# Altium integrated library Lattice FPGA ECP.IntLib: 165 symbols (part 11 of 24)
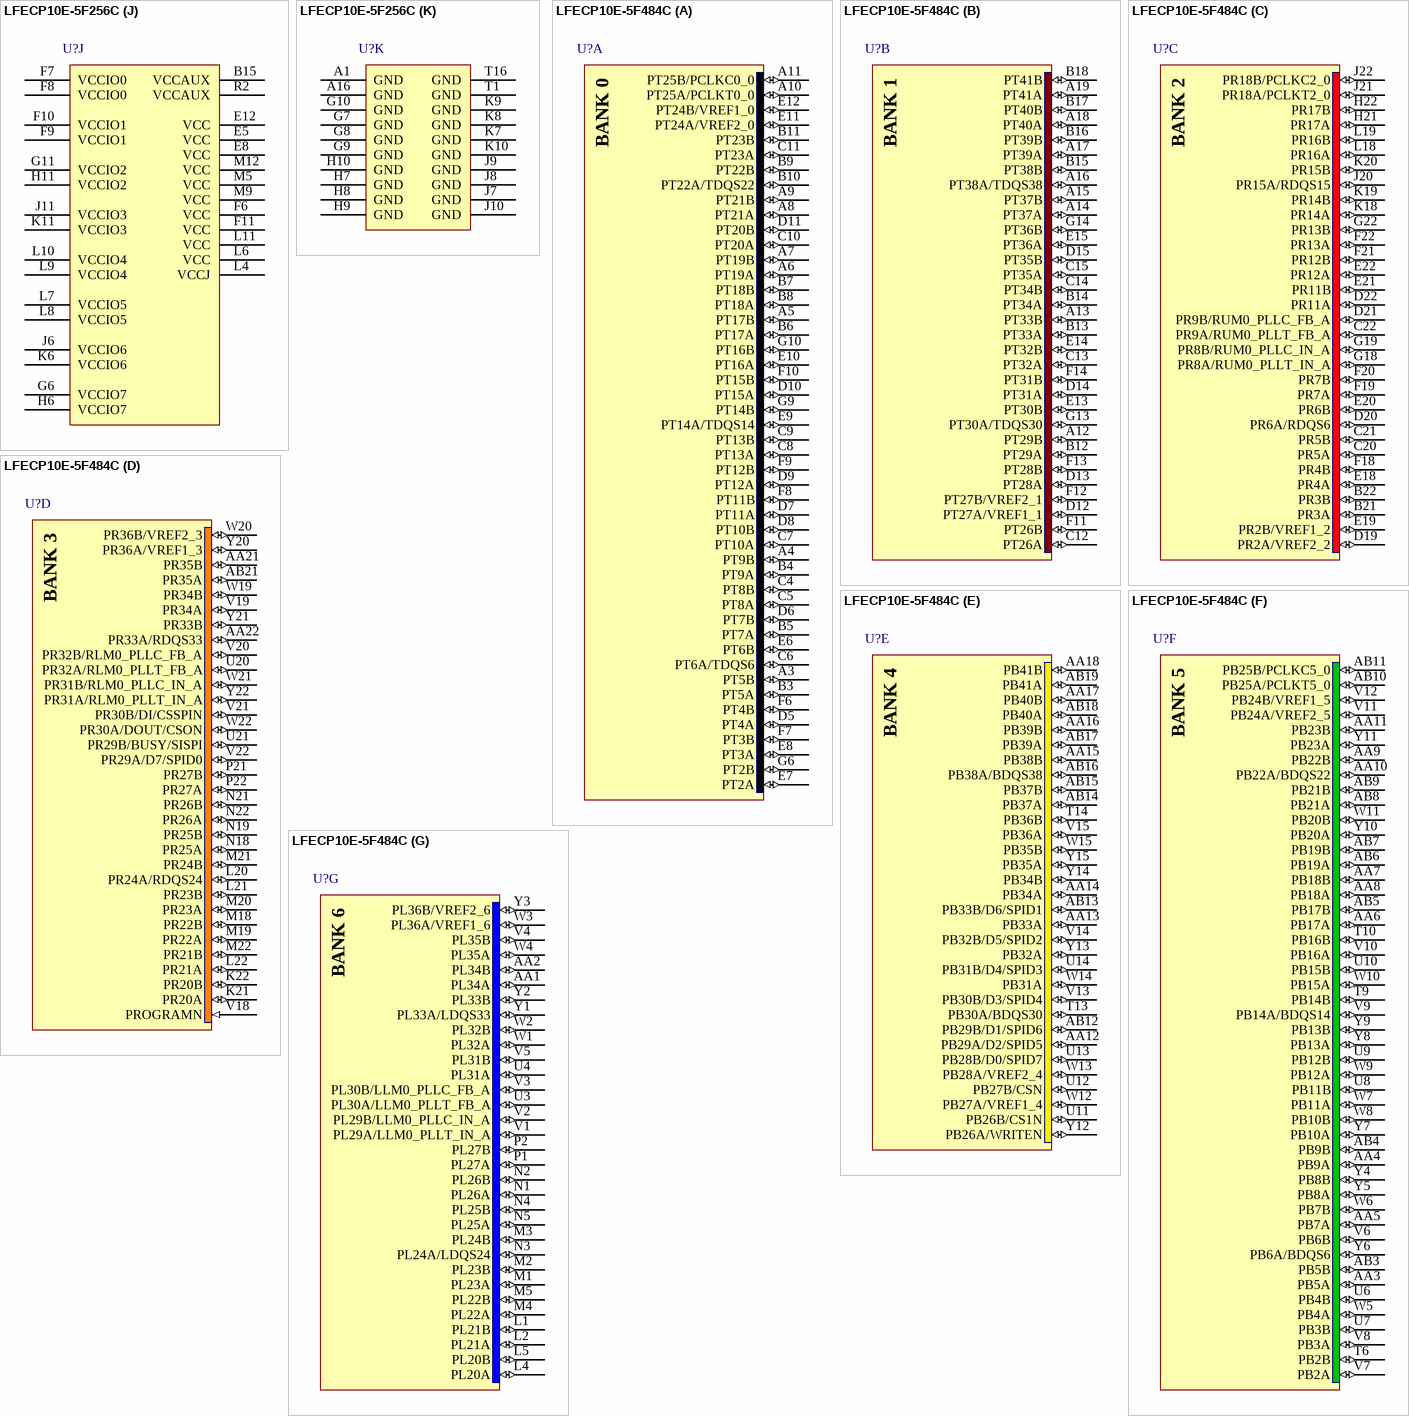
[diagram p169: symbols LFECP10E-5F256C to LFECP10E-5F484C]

## LFECP10E-5F256C
designator U?
ECP 1.2V FPGA, 192 I/Os, 4 PLLs, 10.2K LUTs, 5 sysDSP Blocks, 20 18x18 Multipliers, 256-Pin fpBGA, Speed Grade 5, Commercial Temperature Grade
footprint fpBGA256 (BGA, 256-Leads, Body 17x17mm, Pitch 1mm)
3D model ECP10E-fpBGA256 (256-Ball Fine Pitch Ball Grid Array (fpBGA256))
part A pins: A2 PT13A (io), A3 PT13B (io), A4 PT14A/TDQS14 (io), A5 PT14B (io), A6 PT18A (io), A7 PT18B (io), A8 PT21A (io), A9 PT21B (io), A10 PT25B/PCLKC0_0 (io), B2 PT12B (io), B3 PT12A (io), B4 PT10A (io), B5 PT15A (io), B6 PT15B (io), B7 PT20A (io), B8 PT20B (io), B9 PT24A/VREF2_0 (io), B10 PT25A/PCLKT0_0 (io), C4 PT10B (io), C5 PT11A (io), C6 PT16A (io), C7 PT19A (io), C8 PT22A/TDQS22 (io), C9 PT24B/VREF1_0 (io), D5 PT11B (io), D6 PT16B (io), D7 PT19B (io), D8 PT22B (io), D9 PT23A (io), E6 PT17A (io), E7 PT17B (io), E9 PT23B (io)
part B pins: A11 PT26B (io), A12 PT27B/VREF2_1 (io), A13 PT29A (io), A14 PT29B (io), A15 PT32B (io), B11 PT26A (io), B12 PT27A/VREF1_1 (io), B13 PT34B (io), B14 PT32A (io), C10 PT28A (io), C11 PT31A (io), C12 PT33B (io), C13 PT34A (io), D10 PT28B (io), D11 PT31B (io), D12 PT33A (io), E10 PT30B (io), E11 PT30A/TDQS30 (io)
part C pins: B16 PR13A (io), C14 PR12A (io), C15 PR12B (io), C16 PR13B (io), D13 PR2A/VREF2_2 (io), D14 PR2B/VREF1_2 (io), D15 PR15A (io), D16 PR15B (io), E13 PR16A (io), E14 PR14A (io), F12 PR16B (io), F13 PR17A (io), F14 PR14B (io), G12 PR18A/PCLKT2_0 (io), G13 PR17B (io), H12 PR18B/PCLKC2_0 (io)
part D pins: E15 PR20A (io), E16 PR20B (io), F15 PR23A (io), F16 PR23B (io), G14 PR21A (io), G15 PR26A (io), G16 PR26B (io), H13 PR22A (io), H14 PR21B (io), H15 PR27A (io), H16 PR27B (io), J12 PR25A (io), J13 PR22B (io), J14 PR24B (io), J15 PR24A/RDQS24 (io), J16 PR29A/D7/SPID0 (io), K12 PR25B (io), K16 PR29B/BUSY/SISPI (io), L16 PR30A/DOUT/CSON (io), M13 PR33B (io), M14 PR33A/RDQS33 (io), M15 PR31A/RLM0_PLLT_IN_A (io), M16 PR30B/DI/CSSPIN (io), N13 PR36B/VREF2_3 (io), N14 PR36A/VREF1_3 (io), N15 PR31B/RLM0_PLLC_IN_A (io), N16 PR32A/RLM0_PLLT_FB_A (io), P14 PR35B (io), P15 PR35A (io), P16 PR32B/RLM0_PLLC_FB_A (io), R15 PR34B (io), R16 PR34A (io)
part E pins: M10 PB29A/D2/SPID5 (io), M11 PB29B/D1/SPID6 (io), N10 PB27B/CSN (io), N11 PB33A (io), N12 PB33B/D6/SPID1 (io), P10 PB27A/VREF1_4 (io), P11 PB30B/D3/SPID4 (io), P12 PB32A (io), P13 PB32B/D5/SPID2 (io), R11 PB30A/BDQS30 (io), R12 PB34A (io), R13 PB31A (io), R14 PB31B/D4/SPID3 (io), T12 PB26A/WRITEN (io), T13 PB26B/CS1N (io), T14 PB28A/VREF2_4 (io), T15 PB28B/D0/SPID7 (io)
part F pins: M6 PB16B (io), M7 PB20A (io), M8 PB20B (io), N5 PB10B (io), N6 PB16A (io), N7 PB18B (io), N8 PB22B (io), N9 PB24B/VREF1_5 (io), P4 PB10A (io), P5 PB11A (io), P6 PB11B (io), P7 PB18A (io), P8 PB22A/BDQS22 (io), P9 PB24A/VREF2_5 (io), R3 PB12B (io), R4 PB12A (io), R5 PB14A/BDQS14 (io), R6 PB14B (io), R7 PB19A (io), R8 PB19B (io), R9 PB23A (io), R10 PB23B (io), T2 PB13A (io), T3 PB13B (io), T4 PB15A (io), T5 PB15B (io), T6 PB17A (io), T7 PB17B (io), T8 PB21A (io), T9 PB21B (io), T10 PB25A/PCLKT5_0 (io), T11 PB25B/PCLKC5_0 (io)
part G pins: F1 PL21B (io), F2 PL21A (io), G1 PL23B (io), G2 PL23A (io), G5 PL20A (io), H1 PL26B (io), H2 PL26A (io), H3 PL22B (io), H4 PL22A (io), H5 PL20B (io), J1 PL27B (io), J2 PL27A (io), J3 PL24B (io), J4 PL24A/LDQS24 (io), J5 PL25A (io), K1 PL29B/LLM0_PLLC_IN_A (io), K2 PL29A/LLM0_PLLT_IN_A (io), K5 PL25B (io), L1 PL30B/LLM0_PLLC_FB_A (io), L2 PL30A/LLM0_PLLT_FB_A (io), M1 PL31B (io), M2 PL31A (io), M3 PL33B (io), M4 PL33A/LDQS33 (io), N1 PL32A (io), N2 PL32B (io), N3 PL36A/VREF1_6 (io), N4 PL36B/VREF2_6 (io), P1 PL34A (io), P2 PL35A (io), P3 PL35B (io), R1 PL34B (io)
part H pins: B1 PL13A (io), C1 PL13B (io), C2 PL12B (io), C3 PL12A (io), D1 PL17B (io), D2 PL17A (io), D3 PL2B/VREF1_7 (io), D4 PL2A/VREF2_7 (io), E1 PL18A/PCLKT7_0 (io), E2 PL18B/PCLKC7_0 (io), E3 PL14A (io), E4 PL14B (io), F4 PL15A/LDQS15 (io), F5 PL15B (io), G3 PL16B (io), G4 PL16A (io)
part I pins: F3 XRES, K3 TDI (in), K4 TCK (in), K13 PROGRAMN (in), K14 DONE (io), K15 INITN (io), L3 TMS (in), L5 TDO (out), L12 CFG2 (in), L13 CFG0 (in), L14 CFG1 (in), L15 CCLK (io)
part J pins: B15 VCCAUX (power), E5 VCC (power), E8 VCC (power), E12 VCC (power), F6 VCC (power), F7 VCCIO0 (power), F8 VCCIO0 (power), F9 VCCIO1 (power), F10 VCCIO1 (power), F11 VCC (power), G6 VCCIO7 (power), G11 VCCIO2 (power), H6 VCCIO7 (power), H11 VCCIO2 (power), J6 VCCIO6 (power), J11 VCCIO3 (power), K6 VCCIO6 (power), K11 VCCIO3 (power), L4 VCCJ (power), L6 VCC (power), L7 VCCIO5 (power), L8 VCCIO5 (power), L9 VCCIO4 (power), L10 VCCIO4 (power), L11 VCC (power), M5 VCC (power), M9 VCC (power), M12 VCC (power), R2 VCCAUX (power)
part K pins: A1 GND (power), A16 GND (power), G7 GND (power), G8 GND (power), G9 GND (power), G10 GND (power), H7 GND (power), H8 GND (power), H9 GND (power), H10 GND (power), J7 GND (power), J8 GND (power), J9 GND (power), J10 GND (power), K7 GND (power), K8 GND (power), K9 GND (power), K10 GND (power), T1 GND (power), T16 GND (power)

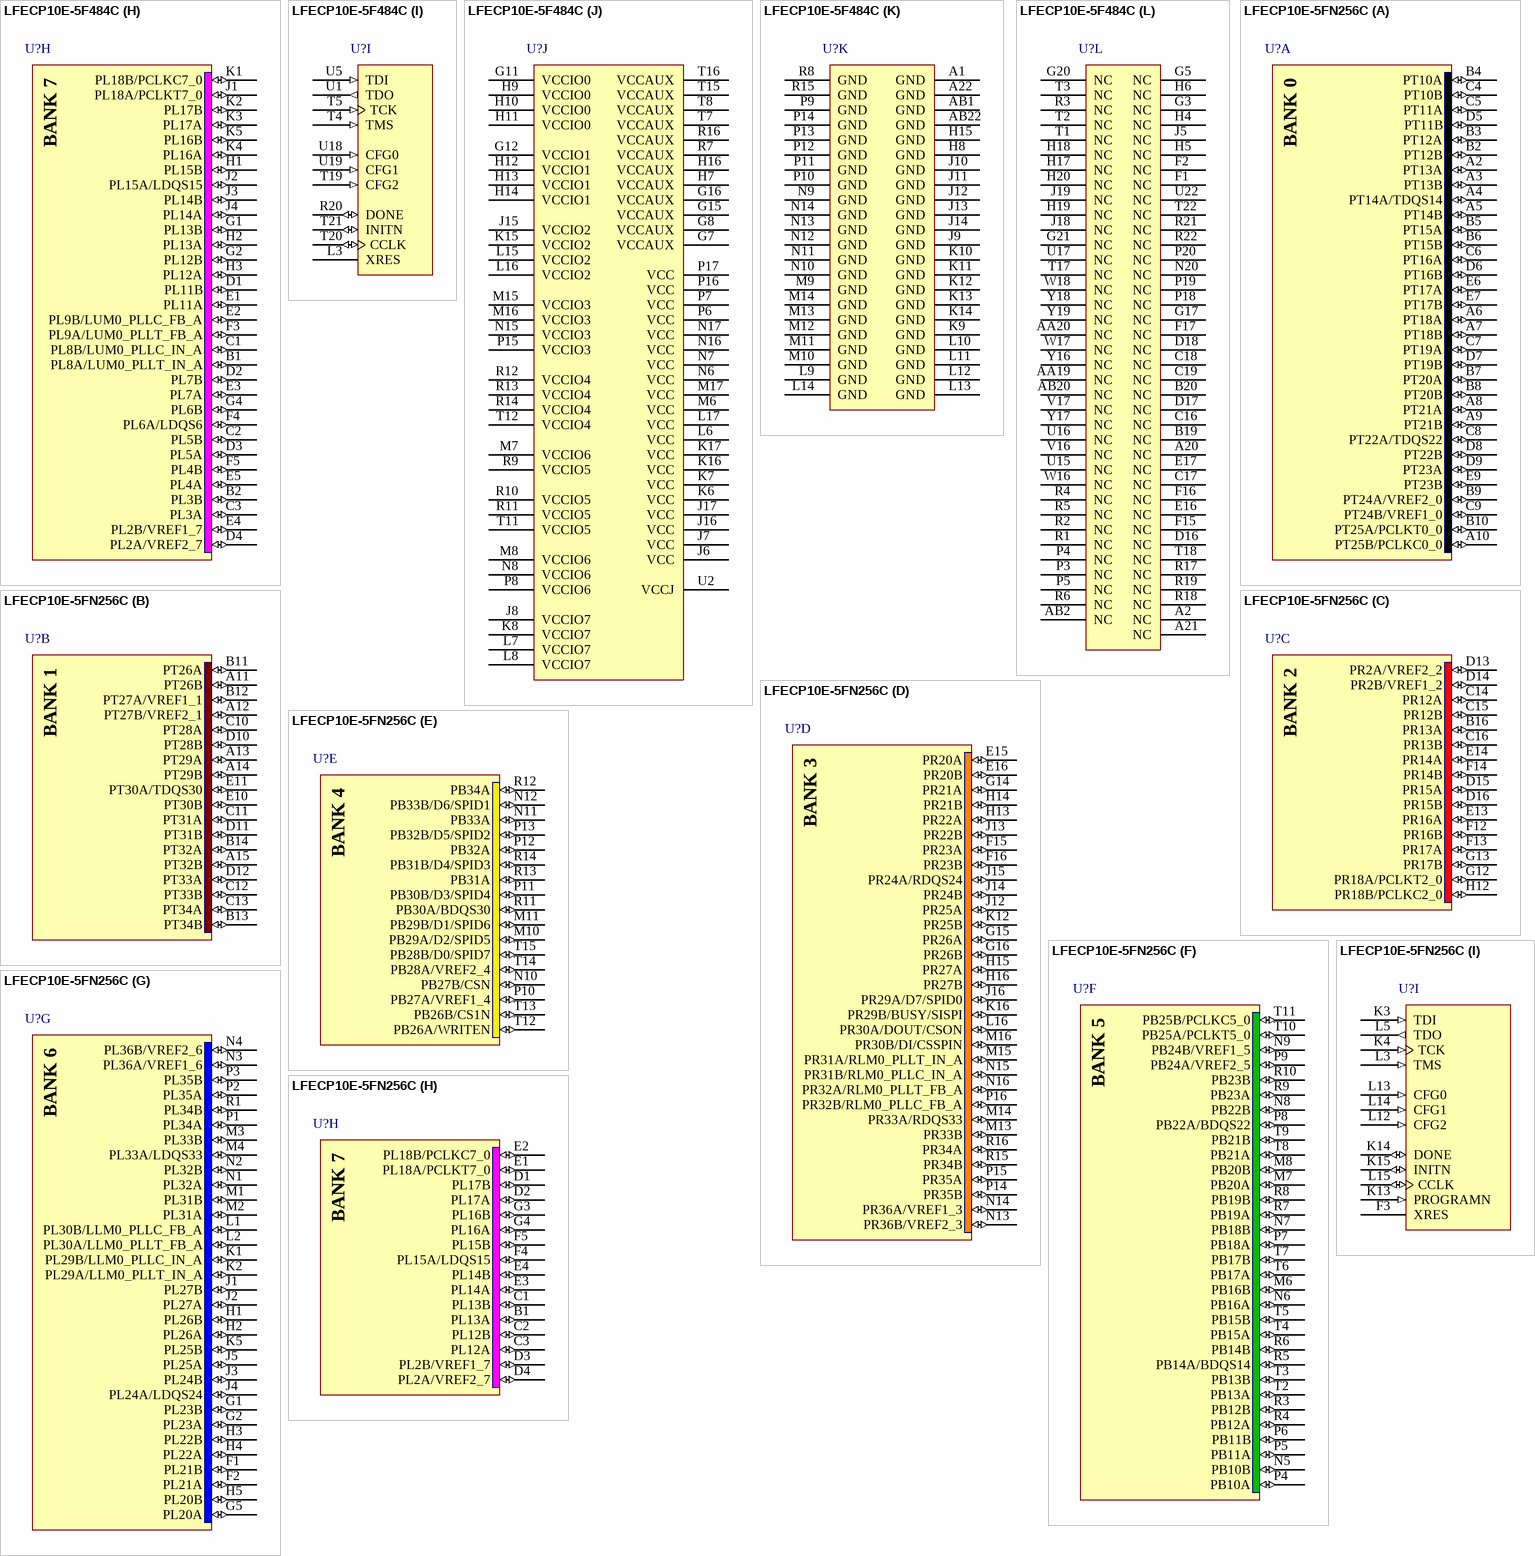
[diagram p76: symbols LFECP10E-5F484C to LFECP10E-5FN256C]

## LFECP10E-5F484C
designator U?
ECP 1.2V FPGA, 288 I/Os, 4 PLLs, 10.2K LUTs, 5 sysDSP Blocks, 20 18x18 Multipliers, 484-Pin fpBGA, Speed Grade 5, Commercial Temperature Grade
footprint fpBGA484 (BGA, 484-Leads, Body 23x23mm, Pitch 1mm)
3D model ECP10E-fpBGA484 (484-Ball Fine Pitch Ball Grid Array (fpBGA484))
part A pins: A3 PT5B (io), A4 PT9B (io), A5 PT17B (io), A6 PT19A (io), A7 PT19B (io), A8 PT21A (io), A9 PT21B (io), A10 PT25A/PCLKT0_0 (io), A11 PT25B/PCLKC0_0 (io), B3 PT5A (io), B4 PT9A (io), B5 PT7A (io), B6 PT17A (io), B7 PT18B (io), B8 PT18A (io), B9 PT22B (io), B10 PT22A/TDQS22 (io), B11 PT23B (io), C4 PT8B (io), C5 PT8A (io), C6 PT6A/TDQS6 (io), C7 PT10A (io), C8 PT13A (io), C9 PT13B (io), C10 PT20A (io), C11 PT23A (io), D5 PT4A (io), D6 PT7B (io), D7 PT11A (io), D8 PT10B (io), D9 PT12A (io), D10 PT15A (io), D11 PT20B (io), E6 PT6B (io), E7 PT2A (io), E8 PT3A (io), E9 PT14A/TDQS14 (io), E10 PT16A (io), E11 PT24A/VREF2_0 (io), E12 PT24B/VREF1_0 (io), F6 PT4B (io), F7 PT3B (io), F8 PT11B (io), F9 PT12B (io), F10 PT15B (io), G6 PT2B (io), G9 PT14B (io), G10 PT16B (io)
part B pins: A12 PT29B (io), A13 PT33B (io), A14 PT37A (io), A15 PT37B (io), A16 PT38A/TDQS38 (io), A17 PT39A (io), A18 PT40A (io), A19 PT41A (io), B12 PT29A (io), B13 PT33A (io), B14 PT34A (io), B15 PT38B (io), B16 PT39B (io), B17 PT40B (io), B18 PT41B (io), C12 PT26A (io), C13 PT32A (io), C14 PT34B (io), C15 PT35A (io), D12 PT27A/VREF1_1 (io), D13 PT28A (io), D14 PT31A (io), D15 PT35B (io), E13 PT30B (io), E14 PT32B (io), E15 PT36A (io), F11 PT26B (io), F12 PT27B/VREF2_1 (io), F13 PT28B (io), F14 PT31B (io), G13 PT30A/TDQS30 (io), G14 PT36B (io)
part C pins: B21 PR3A (io), B22 PR3B (io), C20 PR5A (io), C21 PR5B (io), C22 PR9A/RUM0_PLLT_FB_A (io), D19 PR2A/VREF2_2 (io), D20 PR6A/RDQS6 (io), D21 PR9B/RUM0_PLLC_FB_A (io), D22 PR11A (io), E18 PR4A (io), E19 PR2B/VREF1_2 (io), E20 PR6B (io), E21 PR11B (io), E22 PR12A (io), F18 PR4B (io), F19 PR7A (io), F20 PR7B (io), F21 PR12B (io), F22 PR13A (io), G18 PR8A/RUM0_PLLT_IN_A (io), G19 PR8B/RUM0_PLLC_IN_A (io), G22 PR13B (io), H21 PR17A (io), H22 PR17B (io), J20 PR15A/RDQS15 (io), J21 PR18A/PCLKT2_0 (io), J22 PR18B/PCLKC2_0 (io), K18 PR14A (io), K19 PR14B (io), K20 PR15B (io), L18 PR16A (io), L19 PR16B (io)
part D pins: AA21 PR35B (io), AA22 PR33A/RDQS33 (io), AB21 PR35A (io), K21 PR20A (io), K22 PR20B (io), L20 PR24A/RDQS24 (io), L21 PR23B (io), L22 PR21A (io), M18 PR22B (io), M19 PR22A (io), M20 PR23A (io), M21 PR24B (io), M22 PR21B (io), N18 PR25A (io), N19 PR25B (io), N21 PR26B (io), N22 PR26A (io), P21 PR27B (io), P22 PR27A (io), U20 PR32A/RLM0_PLLT_FB_A (io), U21 PR29B/BUSY/SISPI (io), V18 PROGRAMN (in), V19 PR34A (io), V20 PR32B/RLM0_PLLC_FB_A (io), V21 PR30B/DI/CSSPIN (io), V22 PR29A/D7/SPID0 (io), W19 PR34B (io), W20 PR36B/VREF2_3 (io), W21 PR31B/RLM0_PLLC_IN_A (io), W22 PR30A/DOUT/CSON (io), Y20 PR36A/VREF1_3 (io), Y21 PR33B (io), Y22 PR31A/RLM0_PLLT_IN_A (io)
part E pins: AA12 PB29A/D2/SPID5 (io), AA13 PB33A (io), AA14 PB34A (io), AA15 PB38B (io), AA16 PB39B (io), AA17 PB40B (io), AA18 PB41B (io), AB12 PB29B/D1/SPID6 (io), AB13 PB33B/D6/SPID1 (io), AB14 PB37A (io), AB15 PB37B (io), AB16 PB38A/BDQS38 (io), AB17 PB39A (io), AB18 PB40A (io), AB19 PB41A (io), T13 PB30A/BDQS30 (io), T14 PB36B (io), U11 PB26B/CS1N (io), U12 PB27B/CSN (io), U13 PB28B/D0/SPID7 (io), U14 PB31B/D4/SPID3 (io), V13 PB30B/D3/SPID4 (io), V14 PB32B/D5/SPID2 (io), V15 PB36A (io), W12 PB27A/VREF1_4 (io), W13 PB28A/VREF2_4 (io), W14 PB31A (io), W15 PB35B (io), Y12 PB26A/WRITEN (io), Y13 PB32A (io), Y14 PB34B (io), Y15 PB35A (io)
part F pins: AA3 PB5A (io), AA4 PB9A (io), AA5 PB7A (io), AA6 PB17A (io), AA7 PB18B (io), AA8 PB18A (io), AA9 PB22B (io), AA10 PB22A/BDQS22 (io), AA11 PB23B (io), AB3 PB5B (io), AB4 PB9B (io), AB5 PB17B (io), AB6 PB19A (io), AB7 PB19B (io), AB8 PB21A (io), AB9 PB21B (io), AB10 PB25A/PCLKT5_0 (io), AB11 PB25B/PCLKC5_0 (io), T6 PB2B (io), T9 PB14B (io), T10 PB16B (io), U6 PB4B (io), U7 PB3B (io), U8 PB11B (io), U9 PB12B (io), U10 PB15B (io), V6 PB6B (io), V7 PB2A (io), V8 PB3A (io), V9 PB14A/BDQS14 (io), V10 PB16A (io), V11 PB24A/VREF2_5 (io), V12 PB24B/VREF1_5 (io), W5 PB4A (io), W6 PB7B (io), W7 PB11A (io), W8 PB10B (io), W9 PB12A (io), W10 PB15A (io), W11 PB20B (io), Y4 PB8B (io), Y5 PB8A (io), Y6 PB6A/BDQS6 (io), Y7 PB10A (io), Y8 PB13A (io), Y9 PB13B (io), Y10 PB20A (io), Y11 PB23A (io)
part G pins: AA1 PL34A (io), AA2 PL34B (io), L1 PL21B (io), L2 PL21A (io), L4 PL20A (io), L5 PL20B (io), M1 PL23A (io), M2 PL23B (io), M3 PL24B (io), M4 PL22A (io), M5 PL22B (io), N1 PL26A (io), N2 PL26B (io), N3 PL24A/LDQS24 (io), N4 PL25B (io), N5 PL25A (io), P1 PL27A (io), P2 PL27B (io), U3 PL30A/LLM0_PLLT_FB_A (io), U4 PL31A (io), V1 PL29A/LLM0_PLLT_IN_A (io), V2 PL29B/LLM0_PLLC_IN_A (io), V3 PL30B/LLM0_PLLC_FB_A (io), V4 PL35B (io), V5 PL31B (io), W1 PL32A (io), W2 PL32B (io), W3 PL36A/VREF1_6 (io), W4 PL35A (io), Y1 PL33A/LDQS33 (io), Y2 PL33B (io), Y3 PL36B/VREF2_6 (io)
part H pins: B1 PL8A/LUM0_PLLT_IN_A (io), B2 PL3B (io), C1 PL8B/LUM0_PLLC_IN_A (io), C2 PL5B (io), C3 PL3A (io), D1 PL11B (io), D2 PL7B (io), D3 PL5A (io), D4 PL2A/VREF2_7 (io), E1 PL11A (io), E2 PL9B/LUM0_PLLC_FB_A (io), E3 PL7A (io), E4 PL2B/VREF1_7 (io), E5 PL4A (io), F3 PL9A/LUM0_PLLT_FB_A (io), F4 PL6A/LDQS6 (io), F5 PL4B (io), G1 PL13B (io), G2 PL12B (io), G4 PL6B (io), H1 PL15B (io), H2 PL13A (io), H3 PL12A (io), J1 PL18A/PCLKT7_0 (io), J2 PL15A/LDQS15 (io), J3 PL14B (io), J4 PL14A (io), K1 PL18B/PCLKC7_0 (io), K2 PL17B (io), K3 PL17A (io), K4 PL16A (io), K5 PL16B (io)
part I pins: L3 XRES, R20 DONE (io), T4 TMS (in), T5 TCK (in), T19 CFG2 (in), T20 CCLK (io), T21 INITN (io), U1 TDO (out), U5 TDI (in), U18 CFG0 (in), U19 CFG1 (in)
part J pins: G7 VCCAUX (power), G8 VCCAUX (power), G11 VCCIO0 (power), G12 VCCIO1 (power), G15 VCCAUX (power), G16 VCCAUX (power), H7 VCCAUX (power), H9 VCCIO0 (power), H10 VCCIO0 (power), H11 VCCIO0 (power), H12 VCCIO1 (power), H13 VCCIO1 (power), H14 VCCIO1 (power), H16 VCCAUX (power), J6 VCC (power), J7 VCC (power), J8 VCCIO7 (power), J15 VCCIO2 (power), J16 VCC (power), J17 VCC (power), K6 VCC (power), K7 VCC (power), K8 VCCIO7 (power), K15 VCCIO2 (power), K16 VCC (power), K17 VCC (power), L6 VCC (power), L7 VCCIO7 (power), L8 VCCIO7 (power), L15 VCCIO2 (power), L16 VCCIO2 (power), L17 VCC (power), M6 VCC (power), M7 VCCIO6 (power), M8 VCCIO6 (power), M15 VCCIO3 (power), M16 VCCIO3 (power), M17 VCC (power), N6 VCC (power), N7 VCC (power), N8 VCCIO6 (power), N15 VCCIO3 (power), N16 VCC (power), N17 VCC (power), P6 VCC (power), P7 VCC (power), P8 VCCIO6 (power), P15 VCCIO3 (power), P16 VCC (power), P17 VCC (power), R7 VCCAUX (power), R9 VCCIO5 (power), R10 VCCIO5 (power), R11 VCCIO5 (power), R12 VCCIO4 (power), R13 VCCIO4 (power), R14 VCCIO4 (power), R16 VCCAUX (power), T7 VCCAUX (power), T8 VCCAUX (power), T11 VCCIO5 (power), T12 VCCIO4 (power), T15 VCCAUX (power), T16 VCCAUX (power), U2 VCCJ (power)
part K pins: A1 GND (power), A22 GND (power), AB1 GND (power), AB22 GND (power), H8 GND (power), H15 GND (power), J9 GND (power), J10 GND (power), J11 GND (power), J12 GND (power), J13 GND (power), J14 GND (power), K9 GND (power), K10 GND (power), K11 GND (power), K12 GND (power), K13 GND (power), K14 GND (power), L9 GND (power), L10 GND (power), L11 GND (power), L12 GND (power), L13 GND (power), L14 GND (power), M9 GND (power), M10 GND (power), M11 GND (power), M12 GND (power), M13 GND (power), M14 GND (power), N9 GND (power), N10 GND (power), N11 GND (power), N12 GND (power), N13 GND (power), N14 GND (power), P9 GND (power), P10 GND (power), P11 GND (power), P12 GND (power), P13 GND (power), P14 GND (power), R8 GND (power), R15 GND (power)
part L pins: A2 NC, A20 NC, A21 NC, AA19 NC, AA20 NC, AB2 NC, AB20 NC, B19 NC, B20 NC, C16 NC, C17 NC, C18 NC, C19 NC, D16 NC, D17 NC, D18 NC, E16 NC, E17 NC, F1 NC, F2 NC, F15 NC, F16 NC, F17 NC, G3 NC, G5 NC, G17 NC, G20 NC, G21 NC, H4 NC, H5 NC, H6 NC, H17 NC, H18 NC, H19 NC, H20 NC, J5 NC, J18 NC, J19 NC, N20 NC, P3 NC, P4 NC, P5 NC, P18 NC, P19 NC, P20 NC, R1 NC, R2 NC, R3 NC, R4 NC, R5 NC, R6 NC, R17 NC, R18 NC, R19 NC, R21 NC, R22 NC, T1 NC, T2 NC, T3 NC, T17 NC, T18 NC, T22 NC, U15 NC, U16 NC, U17 NC, U22 NC, V16 NC, V17 NC, W16 NC, W17 NC, W18 NC, Y16 NC, Y17 NC, Y18 NC, Y19 NC

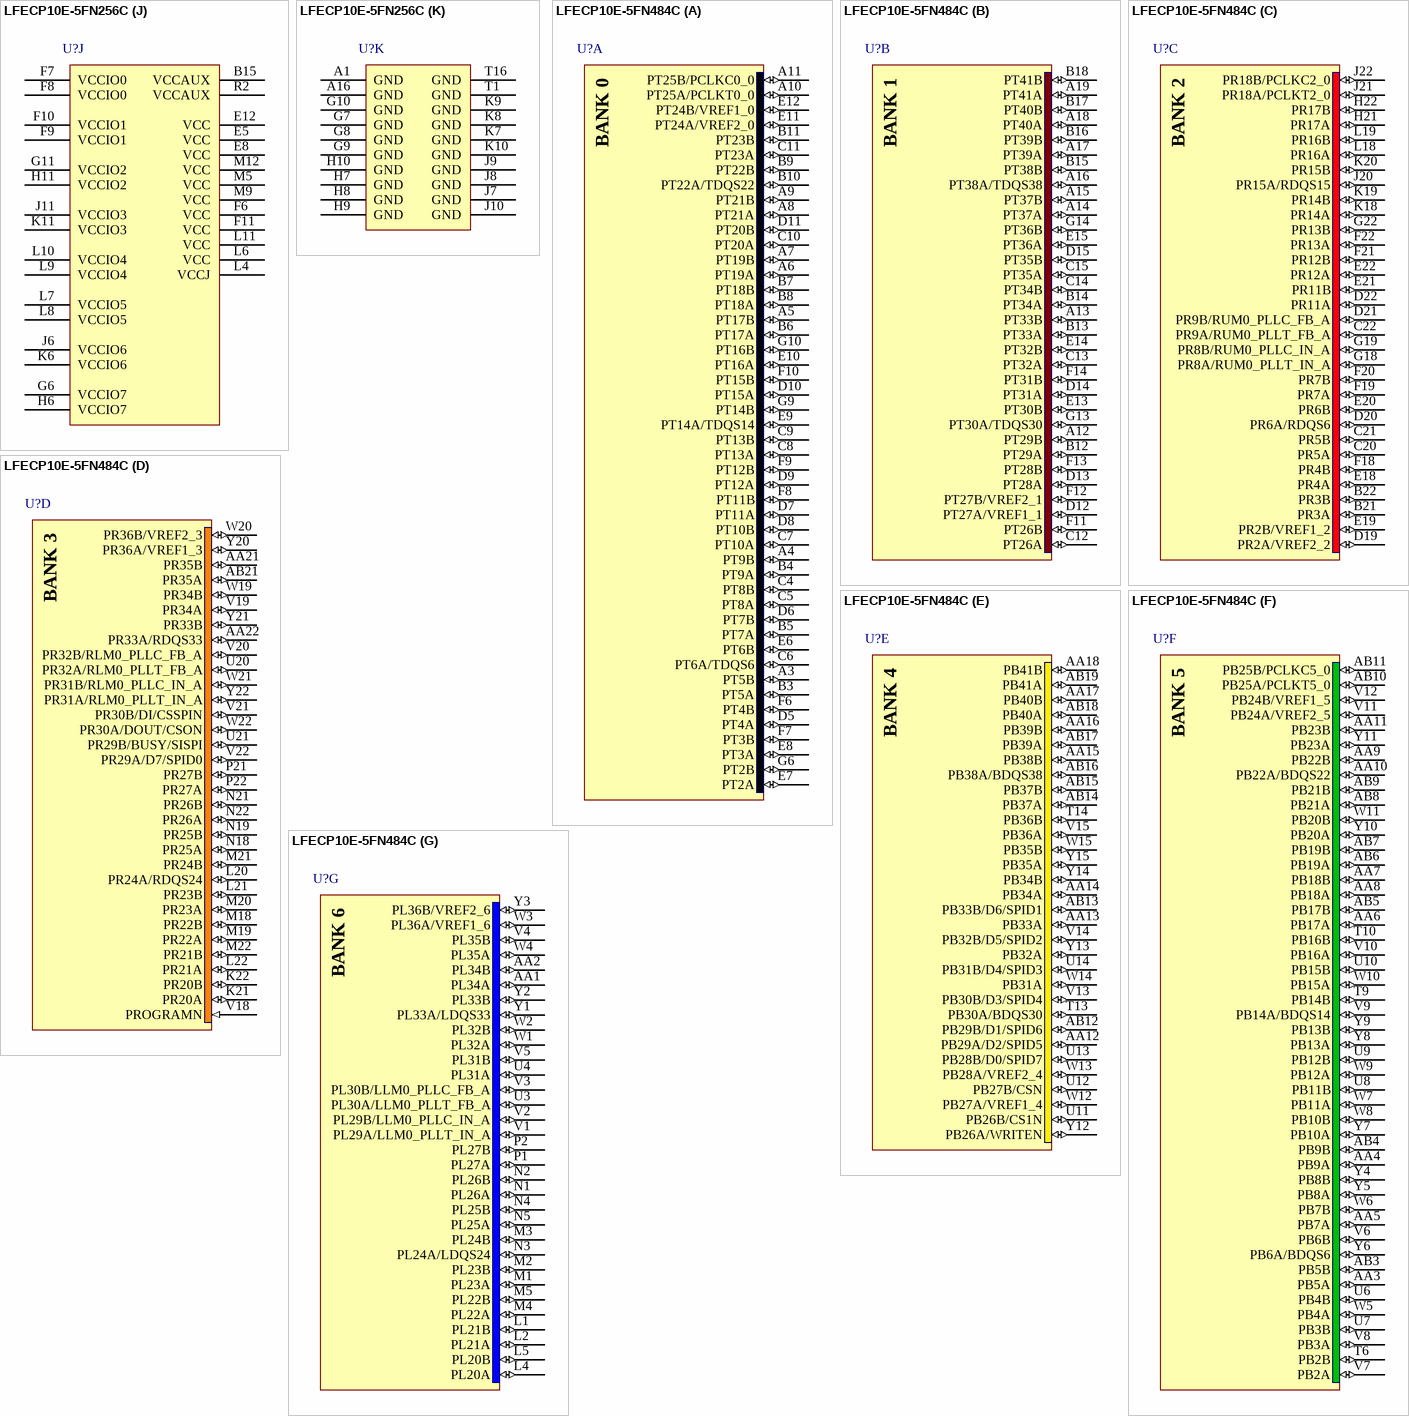
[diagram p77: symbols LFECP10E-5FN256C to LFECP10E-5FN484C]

## LFECP10E-5FN256C
designator U?
ECP 1.2V FPGA, 195 I/Os, 4 PLLs, 10.2K LUTs, 5 sysDSP Blocks, 20 18x18 Multipliers, 256-Pin fpBGA, Pb-Free, Speed Grade 5, Commercial Temperature Grade
footprint fpBGA256 (BGA, 256-Leads, Body 17x17mm, Pitch 1mm)
3D model ECP10E-fpBGA256 (256-Ball Fine Pitch Ball Grid Array (fpBGA256))
part A pins: A2 PT13A (io), A3 PT13B (io), A4 PT14A/TDQS14 (io), A5 PT14B (io), A6 PT18A (io), A7 PT18B (io), A8 PT21A (io), A9 PT21B (io), A10 PT25B/PCLKC0_0 (io), B2 PT12B (io), B3 PT12A (io), B4 PT10A (io), B5 PT15A (io), B6 PT15B (io), B7 PT20A (io), B8 PT20B (io), B9 PT24A/VREF2_0 (io), B10 PT25A/PCLKT0_0 (io), C4 PT10B (io), C5 PT11A (io), C6 PT16A (io), C7 PT19A (io), C8 PT22A/TDQS22 (io), C9 PT24B/VREF1_0 (io), D5 PT11B (io), D6 PT16B (io), D7 PT19B (io), D8 PT22B (io), D9 PT23A (io), E6 PT17A (io), E7 PT17B (io), E9 PT23B (io)
part B pins: A11 PT26B (io), A12 PT27B/VREF2_1 (io), A13 PT29A (io), A14 PT29B (io), A15 PT32B (io), B11 PT26A (io), B12 PT27A/VREF1_1 (io), B13 PT34B (io), B14 PT32A (io), C10 PT28A (io), C11 PT31A (io), C12 PT33B (io), C13 PT34A (io), D10 PT28B (io), D11 PT31B (io), D12 PT33A (io), E10 PT30B (io), E11 PT30A/TDQS30 (io)
part C pins: B16 PR13A (io), C14 PR12A (io), C15 PR12B (io), C16 PR13B (io), D13 PR2A/VREF2_2 (io), D14 PR2B/VREF1_2 (io), D15 PR15A (io), D16 PR15B (io), E13 PR16A (io), E14 PR14A (io), F12 PR16B (io), F13 PR17A (io), F14 PR14B (io), G12 PR18A/PCLKT2_0 (io), G13 PR17B (io), H12 PR18B/PCLKC2_0 (io)
part D pins: E15 PR20A (io), E16 PR20B (io), F15 PR23A (io), F16 PR23B (io), G14 PR21A (io), G15 PR26A (io), G16 PR26B (io), H13 PR22A (io), H14 PR21B (io), H15 PR27A (io), H16 PR27B (io), J12 PR25A (io), J13 PR22B (io), J14 PR24B (io), J15 PR24A/RDQS24 (io), J16 PR29A/D7/SPID0 (io), K12 PR25B (io), K16 PR29B/BUSY/SISPI (io), L16 PR30A/DOUT/CSON (io), M13 PR33B (io), M14 PR33A/RDQS33 (io), M15 PR31A/RLM0_PLLT_IN_A (io), M16 PR30B/DI/CSSPIN (io), N13 PR36B/VREF2_3 (io), N14 PR36A/VREF1_3 (io), N15 PR31B/RLM0_PLLC_IN_A (io), N16 PR32A/RLM0_PLLT_FB_A (io), P14 PR35B (io), P15 PR35A (io), P16 PR32B/RLM0_PLLC_FB_A (io), R15 PR34B (io), R16 PR34A (io)
part E pins: M10 PB29A/D2/SPID5 (io), M11 PB29B/D1/SPID6 (io), N10 PB27B/CSN (io), N11 PB33A (io), N12 PB33B/D6/SPID1 (io), P10 PB27A/VREF1_4 (io), P11 PB30B/D3/SPID4 (io), P12 PB32A (io), P13 PB32B/D5/SPID2 (io), R11 PB30A/BDQS30 (io), R12 PB34A (io), R13 PB31A (io), R14 PB31B/D4/SPID3 (io), T12 PB26A/WRITEN (io), T13 PB26B/CS1N (io), T14 PB28A/VREF2_4 (io), T15 PB28B/D0/SPID7 (io)
part F pins: M6 PB16B (io), M7 PB20A (io), M8 PB20B (io), N5 PB10B (io), N6 PB16A (io), N7 PB18B (io), N8 PB22B (io), N9 PB24B/VREF1_5 (io), P4 PB10A (io), P5 PB11A (io), P6 PB11B (io), P7 PB18A (io), P8 PB22A/BDQS22 (io), P9 PB24A/VREF2_5 (io), R3 PB12B (io), R4 PB12A (io), R5 PB14A/BDQS14 (io), R6 PB14B (io), R7 PB19A (io), R8 PB19B (io), R9 PB23A (io), R10 PB23B (io), T2 PB13A (io), T3 PB13B (io), T4 PB15A (io), T5 PB15B (io), T6 PB17A (io), T7 PB17B (io), T8 PB21A (io), T9 PB21B (io), T10 PB25A/PCLKT5_0 (io), T11 PB25B/PCLKC5_0 (io)
part G pins: F1 PL21B (io), F2 PL21A (io), G1 PL23B (io), G2 PL23A (io), G5 PL20A (io), H1 PL26B (io), H2 PL26A (io), H3 PL22B (io), H4 PL22A (io), H5 PL20B (io), J1 PL27B (io), J2 PL27A (io), J3 PL24B (io), J4 PL24A/LDQS24 (io), J5 PL25A (io), K1 PL29B/LLM0_PLLC_IN_A (io), K2 PL29A/LLM0_PLLT_IN_A (io), K5 PL25B (io), L1 PL30B/LLM0_PLLC_FB_A (io), L2 PL30A/LLM0_PLLT_FB_A (io), M1 PL31B (io), M2 PL31A (io), M3 PL33B (io), M4 PL33A/LDQS33 (io), N1 PL32A (io), N2 PL32B (io), N3 PL36A/VREF1_6 (io), N4 PL36B/VREF2_6 (io), P1 PL34A (io), P2 PL35A (io), P3 PL35B (io), R1 PL34B (io)
part H pins: B1 PL13A (io), C1 PL13B (io), C2 PL12B (io), C3 PL12A (io), D1 PL17B (io), D2 PL17A (io), D3 PL2B/VREF1_7 (io), D4 PL2A/VREF2_7 (io), E1 PL18A/PCLKT7_0 (io), E2 PL18B/PCLKC7_0 (io), E3 PL14A (io), E4 PL14B (io), F4 PL15A/LDQS15 (io), F5 PL15B (io), G3 PL16B (io), G4 PL16A (io)
part I pins: F3 XRES, K3 TDI (in), K4 TCK (in), K13 PROGRAMN (in), K14 DONE (io), K15 INITN (io), L3 TMS (in), L5 TDO (out), L12 CFG2 (in), L13 CFG0 (in), L14 CFG1 (in), L15 CCLK (io)
part J pins: B15 VCCAUX (power), E5 VCC (power), E8 VCC (power), E12 VCC (power), F6 VCC (power), F7 VCCIO0 (power), F8 VCCIO0 (power), F9 VCCIO1 (power), F10 VCCIO1 (power), F11 VCC (power), G6 VCCIO7 (power), G11 VCCIO2 (power), H6 VCCIO7 (power), H11 VCCIO2 (power), J6 VCCIO6 (power), J11 VCCIO3 (power), K6 VCCIO6 (power), K11 VCCIO3 (power), L4 VCCJ (power), L6 VCC (power), L7 VCCIO5 (power), L8 VCCIO5 (power), L9 VCCIO4 (power), L10 VCCIO4 (power), L11 VCC (power), M5 VCC (power), M9 VCC (power), M12 VCC (power), R2 VCCAUX (power)
part K pins: A1 GND (power), A16 GND (power), G7 GND (power), G8 GND (power), G9 GND (power), G10 GND (power), H7 GND (power), H8 GND (power), H9 GND (power), H10 GND (power), J7 GND (power), J8 GND (power), J9 GND (power), J10 GND (power), K7 GND (power), K8 GND (power), K9 GND (power), K10 GND (power), T1 GND (power), T16 GND (power)

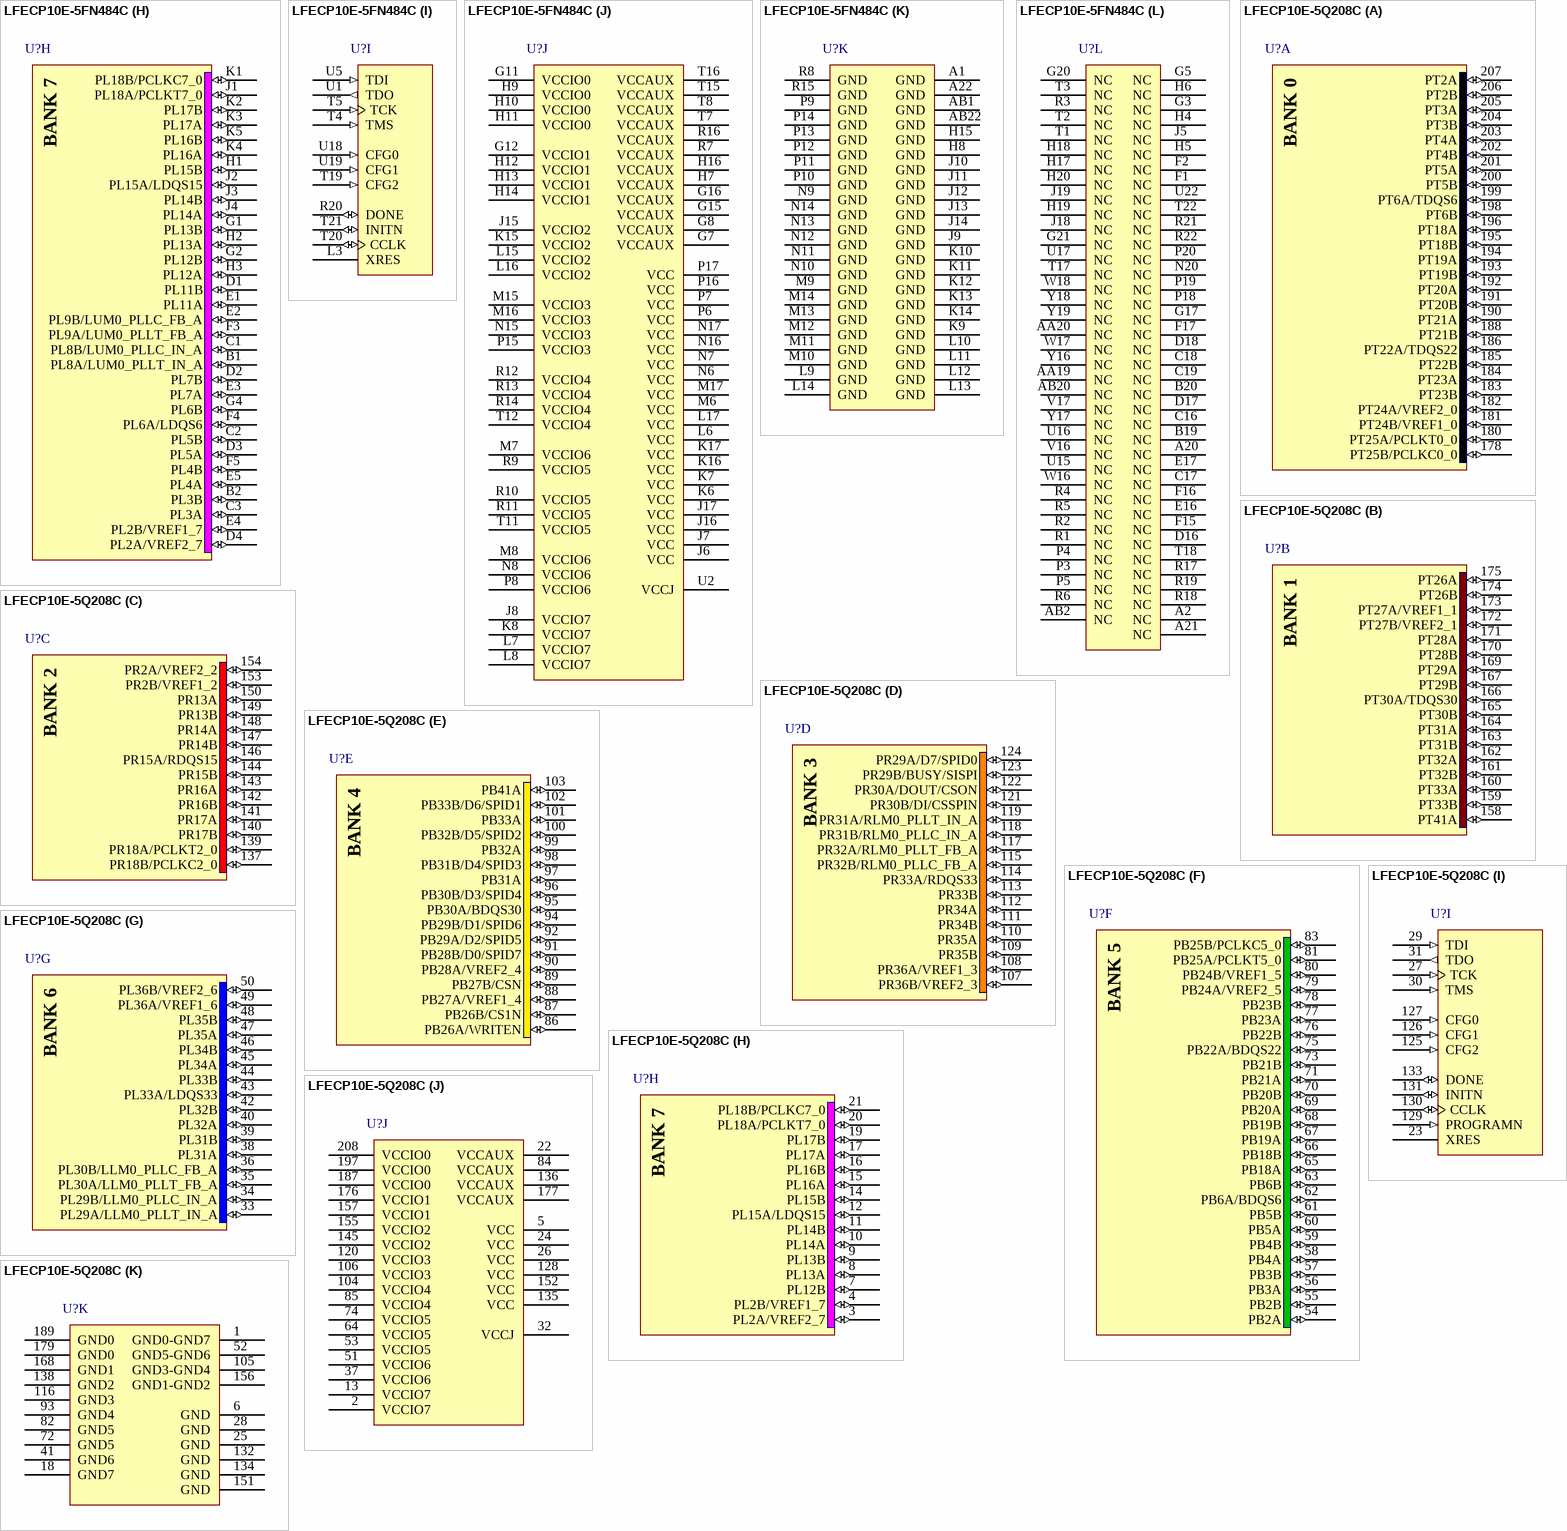
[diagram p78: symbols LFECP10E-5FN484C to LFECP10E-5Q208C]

## LFECP10E-5FN484C
designator U?
ECP 1.2V FPGA, 228 I/Os, 4 PLLs, 10.2K LUTs, 5 sysDSP Blocks, 20 18x18 Multipliers, 484-Pin fpBGA, Pb-Free, Speed Grade 5, Commercial Temperature Grade
footprint fpBGA484 (BGA, 484-Leads, Body 23x23mm, Pitch 1mm)
3D model ECP10E-fpBGA484 (484-Ball Fine Pitch Ball Grid Array (fpBGA484))
part A pins: A3 PT5B (io), A4 PT9B (io), A5 PT17B (io), A6 PT19A (io), A7 PT19B (io), A8 PT21A (io), A9 PT21B (io), A10 PT25A/PCLKT0_0 (io), A11 PT25B/PCLKC0_0 (io), B3 PT5A (io), B4 PT9A (io), B5 PT7A (io), B6 PT17A (io), B7 PT18B (io), B8 PT18A (io), B9 PT22B (io), B10 PT22A/TDQS22 (io), B11 PT23B (io), C4 PT8B (io), C5 PT8A (io), C6 PT6A/TDQS6 (io), C7 PT10A (io), C8 PT13A (io), C9 PT13B (io), C10 PT20A (io), C11 PT23A (io), D5 PT4A (io), D6 PT7B (io), D7 PT11A (io), D8 PT10B (io), D9 PT12A (io), D10 PT15A (io), D11 PT20B (io), E6 PT6B (io), E7 PT2A (io), E8 PT3A (io), E9 PT14A/TDQS14 (io), E10 PT16A (io), E11 PT24A/VREF2_0 (io), E12 PT24B/VREF1_0 (io), F6 PT4B (io), F7 PT3B (io), F8 PT11B (io), F9 PT12B (io), F10 PT15B (io), G6 PT2B (io), G9 PT14B (io), G10 PT16B (io)
part B pins: A12 PT29B (io), A13 PT33B (io), A14 PT37A (io), A15 PT37B (io), A16 PT38A/TDQS38 (io), A17 PT39A (io), A18 PT40A (io), A19 PT41A (io), B12 PT29A (io), B13 PT33A (io), B14 PT34A (io), B15 PT38B (io), B16 PT39B (io), B17 PT40B (io), B18 PT41B (io), C12 PT26A (io), C13 PT32A (io), C14 PT34B (io), C15 PT35A (io), D12 PT27A/VREF1_1 (io), D13 PT28A (io), D14 PT31A (io), D15 PT35B (io), E13 PT30B (io), E14 PT32B (io), E15 PT36A (io), F11 PT26B (io), F12 PT27B/VREF2_1 (io), F13 PT28B (io), F14 PT31B (io), G13 PT30A/TDQS30 (io), G14 PT36B (io)
part C pins: B21 PR3A (io), B22 PR3B (io), C20 PR5A (io), C21 PR5B (io), C22 PR9A/RUM0_PLLT_FB_A (io), D19 PR2A/VREF2_2 (io), D20 PR6A/RDQS6 (io), D21 PR9B/RUM0_PLLC_FB_A (io), D22 PR11A (io), E18 PR4A (io), E19 PR2B/VREF1_2 (io), E20 PR6B (io), E21 PR11B (io), E22 PR12A (io), F18 PR4B (io), F19 PR7A (io), F20 PR7B (io), F21 PR12B (io), F22 PR13A (io), G18 PR8A/RUM0_PLLT_IN_A (io), G19 PR8B/RUM0_PLLC_IN_A (io), G22 PR13B (io), H21 PR17A (io), H22 PR17B (io), J20 PR15A/RDQS15 (io), J21 PR18A/PCLKT2_0 (io), J22 PR18B/PCLKC2_0 (io), K18 PR14A (io), K19 PR14B (io), K20 PR15B (io), L18 PR16A (io), L19 PR16B (io)
part D pins: AA21 PR35B (io), AA22 PR33A/RDQS33 (io), AB21 PR35A (io), K21 PR20A (io), K22 PR20B (io), L20 PR24A/RDQS24 (io), L21 PR23B (io), L22 PR21A (io), M18 PR22B (io), M19 PR22A (io), M20 PR23A (io), M21 PR24B (io), M22 PR21B (io), N18 PR25A (io), N19 PR25B (io), N21 PR26B (io), N22 PR26A (io), P21 PR27B (io), P22 PR27A (io), U20 PR32A/RLM0_PLLT_FB_A (io), U21 PR29B/BUSY/SISPI (io), V18 PROGRAMN (in), V19 PR34A (io), V20 PR32B/RLM0_PLLC_FB_A (io), V21 PR30B/DI/CSSPIN (io), V22 PR29A/D7/SPID0 (io), W19 PR34B (io), W20 PR36B/VREF2_3 (io), W21 PR31B/RLM0_PLLC_IN_A (io), W22 PR30A/DOUT/CSON (io), Y20 PR36A/VREF1_3 (io), Y21 PR33B (io), Y22 PR31A/RLM0_PLLT_IN_A (io)
part E pins: AA12 PB29A/D2/SPID5 (io), AA13 PB33A (io), AA14 PB34A (io), AA15 PB38B (io), AA16 PB39B (io), AA17 PB40B (io), AA18 PB41B (io), AB12 PB29B/D1/SPID6 (io), AB13 PB33B/D6/SPID1 (io), AB14 PB37A (io), AB15 PB37B (io), AB16 PB38A/BDQS38 (io), AB17 PB39A (io), AB18 PB40A (io), AB19 PB41A (io), T13 PB30A/BDQS30 (io), T14 PB36B (io), U11 PB26B/CS1N (io), U12 PB27B/CSN (io), U13 PB28B/D0/SPID7 (io), U14 PB31B/D4/SPID3 (io), V13 PB30B/D3/SPID4 (io), V14 PB32B/D5/SPID2 (io), V15 PB36A (io), W12 PB27A/VREF1_4 (io), W13 PB28A/VREF2_4 (io), W14 PB31A (io), W15 PB35B (io), Y12 PB26A/WRITEN (io), Y13 PB32A (io), Y14 PB34B (io), Y15 PB35A (io)
part F pins: AA3 PB5A (io), AA4 PB9A (io), AA5 PB7A (io), AA6 PB17A (io), AA7 PB18B (io), AA8 PB18A (io), AA9 PB22B (io), AA10 PB22A/BDQS22 (io), AA11 PB23B (io), AB3 PB5B (io), AB4 PB9B (io), AB5 PB17B (io), AB6 PB19A (io), AB7 PB19B (io), AB8 PB21A (io), AB9 PB21B (io), AB10 PB25A/PCLKT5_0 (io), AB11 PB25B/PCLKC5_0 (io), T6 PB2B (io), T9 PB14B (io), T10 PB16B (io), U6 PB4B (io), U7 PB3B (io), U8 PB11B (io), U9 PB12B (io), U10 PB15B (io), V6 PB6B (io), V7 PB2A (io), V8 PB3A (io), V9 PB14A/BDQS14 (io), V10 PB16A (io), V11 PB24A/VREF2_5 (io), V12 PB24B/VREF1_5 (io), W5 PB4A (io), W6 PB7B (io), W7 PB11A (io), W8 PB10B (io), W9 PB12A (io), W10 PB15A (io), W11 PB20B (io), Y4 PB8B (io), Y5 PB8A (io), Y6 PB6A/BDQS6 (io), Y7 PB10A (io), Y8 PB13A (io), Y9 PB13B (io), Y10 PB20A (io), Y11 PB23A (io)
part G pins: AA1 PL34A (io), AA2 PL34B (io), L1 PL21B (io), L2 PL21A (io), L4 PL20A (io), L5 PL20B (io), M1 PL23A (io), M2 PL23B (io), M3 PL24B (io), M4 PL22A (io), M5 PL22B (io), N1 PL26A (io), N2 PL26B (io), N3 PL24A/LDQS24 (io), N4 PL25B (io), N5 PL25A (io), P1 PL27A (io), P2 PL27B (io), U3 PL30A/LLM0_PLLT_FB_A (io), U4 PL31A (io), V1 PL29A/LLM0_PLLT_IN_A (io), V2 PL29B/LLM0_PLLC_IN_A (io), V3 PL30B/LLM0_PLLC_FB_A (io), V4 PL35B (io), V5 PL31B (io), W1 PL32A (io), W2 PL32B (io), W3 PL36A/VREF1_6 (io), W4 PL35A (io), Y1 PL33A/LDQS33 (io), Y2 PL33B (io), Y3 PL36B/VREF2_6 (io)
part H pins: B1 PL8A/LUM0_PLLT_IN_A (io), B2 PL3B (io), C1 PL8B/LUM0_PLLC_IN_A (io), C2 PL5B (io), C3 PL3A (io), D1 PL11B (io), D2 PL7B (io), D3 PL5A (io), D4 PL2A/VREF2_7 (io), E1 PL11A (io), E2 PL9B/LUM0_PLLC_FB_A (io), E3 PL7A (io), E4 PL2B/VREF1_7 (io), E5 PL4A (io), F3 PL9A/LUM0_PLLT_FB_A (io), F4 PL6A/LDQS6 (io), F5 PL4B (io), G1 PL13B (io), G2 PL12B (io), G4 PL6B (io), H1 PL15B (io), H2 PL13A (io), H3 PL12A (io), J1 PL18A/PCLKT7_0 (io), J2 PL15A/LDQS15 (io), J3 PL14B (io), J4 PL14A (io), K1 PL18B/PCLKC7_0 (io), K2 PL17B (io), K3 PL17A (io), K4 PL16A (io), K5 PL16B (io)
part I pins: L3 XRES, R20 DONE (io), T4 TMS (in), T5 TCK (in), T19 CFG2 (in), T20 CCLK (io), T21 INITN (io), U1 TDO (out), U5 TDI (in), U18 CFG0 (in), U19 CFG1 (in)
part J pins: G7 VCCAUX (power), G8 VCCAUX (power), G11 VCCIO0 (power), G12 VCCIO1 (power), G15 VCCAUX (power), G16 VCCAUX (power), H7 VCCAUX (power), H9 VCCIO0 (power), H10 VCCIO0 (power), H11 VCCIO0 (power), H12 VCCIO1 (power), H13 VCCIO1 (power), H14 VCCIO1 (power), H16 VCCAUX (power), J6 VCC (power), J7 VCC (power), J8 VCCIO7 (power), J15 VCCIO2 (power), J16 VCC (power), J17 VCC (power), K6 VCC (power), K7 VCC (power), K8 VCCIO7 (power), K15 VCCIO2 (power), K16 VCC (power), K17 VCC (power), L6 VCC (power), L7 VCCIO7 (power), L8 VCCIO7 (power), L15 VCCIO2 (power), L16 VCCIO2 (power), L17 VCC (power), M6 VCC (power), M7 VCCIO6 (power), M8 VCCIO6 (power), M15 VCCIO3 (power), M16 VCCIO3 (power), M17 VCC (power), N6 VCC (power), N7 VCC (power), N8 VCCIO6 (power), N15 VCCIO3 (power), N16 VCC (power), N17 VCC (power), P6 VCC (power), P7 VCC (power), P8 VCCIO6 (power), P15 VCCIO3 (power), P16 VCC (power), P17 VCC (power), R7 VCCAUX (power), R9 VCCIO5 (power), R10 VCCIO5 (power), R11 VCCIO5 (power), R12 VCCIO4 (power), R13 VCCIO4 (power), R14 VCCIO4 (power), R16 VCCAUX (power), T7 VCCAUX (power), T8 VCCAUX (power), T11 VCCIO5 (power), T12 VCCIO4 (power), T15 VCCAUX (power), T16 VCCAUX (power), U2 VCCJ (power)
part K pins: A1 GND (power), A22 GND (power), AB1 GND (power), AB22 GND (power), H8 GND (power), H15 GND (power), J9 GND (power), J10 GND (power), J11 GND (power), J12 GND (power), J13 GND (power), J14 GND (power), K9 GND (power), K10 GND (power), K11 GND (power), K12 GND (power), K13 GND (power), K14 GND (power), L9 GND (power), L10 GND (power), L11 GND (power), L12 GND (power), L13 GND (power), L14 GND (power), M9 GND (power), M10 GND (power), M11 GND (power), M12 GND (power), M13 GND (power), M14 GND (power), N9 GND (power), N10 GND (power), N11 GND (power), N12 GND (power), N13 GND (power), N14 GND (power), P9 GND (power), P10 GND (power), P11 GND (power), P12 GND (power), P13 GND (power), P14 GND (power), R8 GND (power), R15 GND (power)
part L pins: A2 NC, A20 NC, A21 NC, AA19 NC, AA20 NC, AB2 NC, AB20 NC, B19 NC, B20 NC, C16 NC, C17 NC, C18 NC, C19 NC, D16 NC, D17 NC, D18 NC, E16 NC, E17 NC, F1 NC, F2 NC, F15 NC, F16 NC, F17 NC, G3 NC, G5 NC, G17 NC, G20 NC, G21 NC, H4 NC, H5 NC, H6 NC, H17 NC, H18 NC, H19 NC, H20 NC, J5 NC, J18 NC, J19 NC, N20 NC, P3 NC, P4 NC, P5 NC, P18 NC, P19 NC, P20 NC, R1 NC, R2 NC, R3 NC, R4 NC, R5 NC, R6 NC, R17 NC, R18 NC, R19 NC, R21 NC, R22 NC, T1 NC, T2 NC, T3 NC, T17 NC, T18 NC, T22 NC, U15 NC, U16 NC, U17 NC, U22 NC, V16 NC, V17 NC, W16 NC, W17 NC, W18 NC, Y16 NC, Y17 NC, Y18 NC, Y19 NC

## LFECP10E-5Q208C
designator U?
ECP 1.2V FPGA, 145 I/Os, 4 PLLs, 10.2K LUTs, 5 sysDSP Blocks, 20 18x18 Multipliers, 208-Pin PQFP, Speed Grade 5, Commercial Temperature Grade; Note: Pins 1, 52, 105 and 156 are double bonded.
footprint PQFP208_N (Shrink QFP, 208-Leads, Body 28x28mm, Pitch 0.5mm, IPC Medium Density)
footprint PQFP208_L (Shrink QFP, 208-Leads, Body 28x28mm, Pitch 0.5mm, IPC High Density)
footprint PQFP208_M (Shrink QFP, 208-Leads, Body 28x28mm, Pitch 0.5mm, IPC Low Density)
3D model ECP10E-PQFP-208 (208-Pin Plastic Quad Flat Pack (PQFP208))
part A pins: 178 PT25B/PCLKC0_0 (io), 180 PT25A/PCLKT0_0 (io), 181 PT24B/VREF1_0 (io), 182 PT24A/VREF2_0 (io), 183 PT23B (io), 184 PT23A (io), 185 PT22B (io), 186 PT22A/TDQS22 (io), 188 PT21B (io), 190 PT21A (io), 191 PT20B (io), 192 PT20A (io), 193 PT19B (io), 194 PT19A (io), 195 PT18B (io), 196 PT18A (io), 198 PT6B (io), 199 PT6A/TDQS6 (io), 200 PT5B (io), 201 PT5A (io), 202 PT4B (io), 203 PT4A (io), 204 PT3B (io), 205 PT3A (io), 206 PT2B (io), 207 PT2A (io)
part B pins: 158 PT41A (io), 159 PT33B (io), 160 PT33A (io), 161 PT32B (io), 162 PT32A (io), 163 PT31B (io), 164 PT31A (io), 165 PT30B (io), 166 PT30A/TDQS30 (io), 167 PT29B (io), 169 PT29A (io), 170 PT28B (io), 171 PT28A (io), 172 PT27B/VREF2_1 (io), 173 PT27A/VREF1_1 (io), 174 PT26B (io), 175 PT26A (io)
part C pins: 137 PR18B/PCLKC2_0 (io), 139 PR18A/PCLKT2_0 (io), 140 PR17B (io), 141 PR17A (io), 142 PR16B (io), 143 PR16A (io), 144 PR15B (io), 146 PR15A/RDQS15 (io), 147 PR14B (io), 148 PR14A (io), 149 PR13B (io), 150 PR13A (io), 153 PR2B/VREF1_2 (io), 154 PR2A/VREF2_2 (io)
part D pins: 107 PR36B/VREF2_3 (io), 108 PR36A/VREF1_3 (io), 109 PR35B (io), 110 PR35A (io), 111 PR34B (io), 112 PR34A (io), 113 PR33B (io), 114 PR33A/RDQS33 (io), 115 PR32B/RLM0_PLLC_FB_A (io), 117 PR32A/RLM0_PLLT_FB_A (io), 118 PR31B/RLM0_PLLC_IN_A (io), 119 PR31A/RLM0_PLLT_IN_A (io), 121 PR30B/DI/CSSPIN (io), 122 PR30A/DOUT/CSON (io), 123 PR29B/BUSY/SISPI (io), 124 PR29A/D7/SPID0 (io)
part E pins: 86 PB26A/WRITEN (io), 87 PB26B/CS1N (io), 88 PB27A/VREF1_4 (io), 89 PB27B/CSN (io), 90 PB28A/VREF2_4 (io), 91 PB28B/D0/SPID7 (io), 92 PB29A/D2/SPID5 (io), 94 PB29B/D1/SPID6 (io), 95 PB30A/BDQS30 (io), 96 PB30B/D3/SPID4 (io), 97 PB31A (io), 98 PB31B/D4/SPID3 (io), 99 PB32A (io), 100 PB32B/D5/SPID2 (io), 101 PB33A (io), 102 PB33B/D6/SPID1 (io), 103 PB41A (io)
part F pins: 54 PB2A (io), 55 PB2B (io), 56 PB3A (io), 57 PB3B (io), 58 PB4A (io), 59 PB4B (io), 60 PB5A (io), 61 PB5B (io), 62 PB6A/BDQS6 (io), 63 PB6B (io), 65 PB18A (io), 66 PB18B (io), 67 PB19A (io), 68 PB19B (io), 69 PB20A (io), 70 PB20B (io), 71 PB21A (io), 73 PB21B (io), 75 PB22A/BDQS22 (io), 76 PB22B (io), 77 PB23A (io), 78 PB23B (io), 79 PB24A/VREF2_5 (io), 80 PB24B/VREF1_5 (io), 81 PB25A/PCLKT5_0 (io), 83 PB25B/PCLKC5_0 (io)
part G pins: 33 PL29A/LLM0_PLLT_IN_A (io), 34 PL29B/LLM0_PLLC_IN_A (io), 35 PL30A/LLM0_PLLT_FB_A (io), 36 PL30B/LLM0_PLLC_FB_A (io), 38 PL31A (io), 39 PL31B (io), 40 PL32A (io), 42 PL32B (io), 43 PL33A/LDQS33 (io), 44 PL33B (io), 45 PL34A (io), 46 PL34B (io), 47 PL35A (io), 48 PL35B (io), 49 PL36A/VREF1_6 (io), 50 PL36B/VREF2_6 (io)
part H pins: 3 PL2A/VREF2_7 (io), 4 PL2B/VREF1_7 (io), 7 PL12B (io), 8 PL13A (io), 9 PL13B (io), 10 PL14A (io), 11 PL14B (io), 12 PL15A/LDQS15 (io), 14 PL15B (io), 15 PL16A (io), 16 PL16B (io), 17 PL17A (io), 19 PL17B (io), 20 PL18A/PCLKT7_0 (io), 21 PL18B/PCLKC7_0 (io)
part I pins: 23 XRES, 27 TCK (in), 29 TDI (in), 30 TMS (in), 31 TDO (out), 125 CFG2 (in), 126 CFG1 (in), 127 CFG0 (in), 129 PROGRAMN (in), 130 CCLK (io), 131 INITN (io), 133 DONE (io)
part J pins: 2 VCCIO7 (power), 5 VCC (power), 13 VCCIO7 (power), 22 VCCAUX (power), 24 VCC (power), 26 VCC (power), 32 VCCJ (power), 37 VCCIO6 (power), 51 VCCIO6 (power), 53 VCCIO5 (power), 64 VCCIO5 (power), 74 VCCIO5 (power), 84 VCCAUX (power), 85 VCCIO4 (power), 104 VCCIO4 (power), 106 VCCIO3 (power), 120 VCCIO3 (power), 128 VCC (power), 135 VCC (power), 136 VCCAUX (power), 145 VCCIO2 (power), 152 VCC (power), 155 VCCIO2 (power), 157 VCCIO1 (power), 176 VCCIO1 (power), 177 VCCAUX (power), 187 VCCIO0 (power), 197 VCCIO0 (power), 208 VCCIO0 (power)
part K pins: 1 GND0-GND7 (power), 6 GND (power), 18 GND7 (power), 25 GND (power), 28 GND (power), 41 GND6 (power), 52 GND5-GND6 (power), 72 GND5 (power), 82 GND5 (power), 93 GND4 (power), 105 GND3-GND4 (power), 116 GND3 (power), 132 GND (power), 134 GND (power), 138 GND2 (power), 151 GND (power), 156 GND1-GND2 (power), 168 GND1 (power), 179 GND0 (power), 189 GND0 (power)

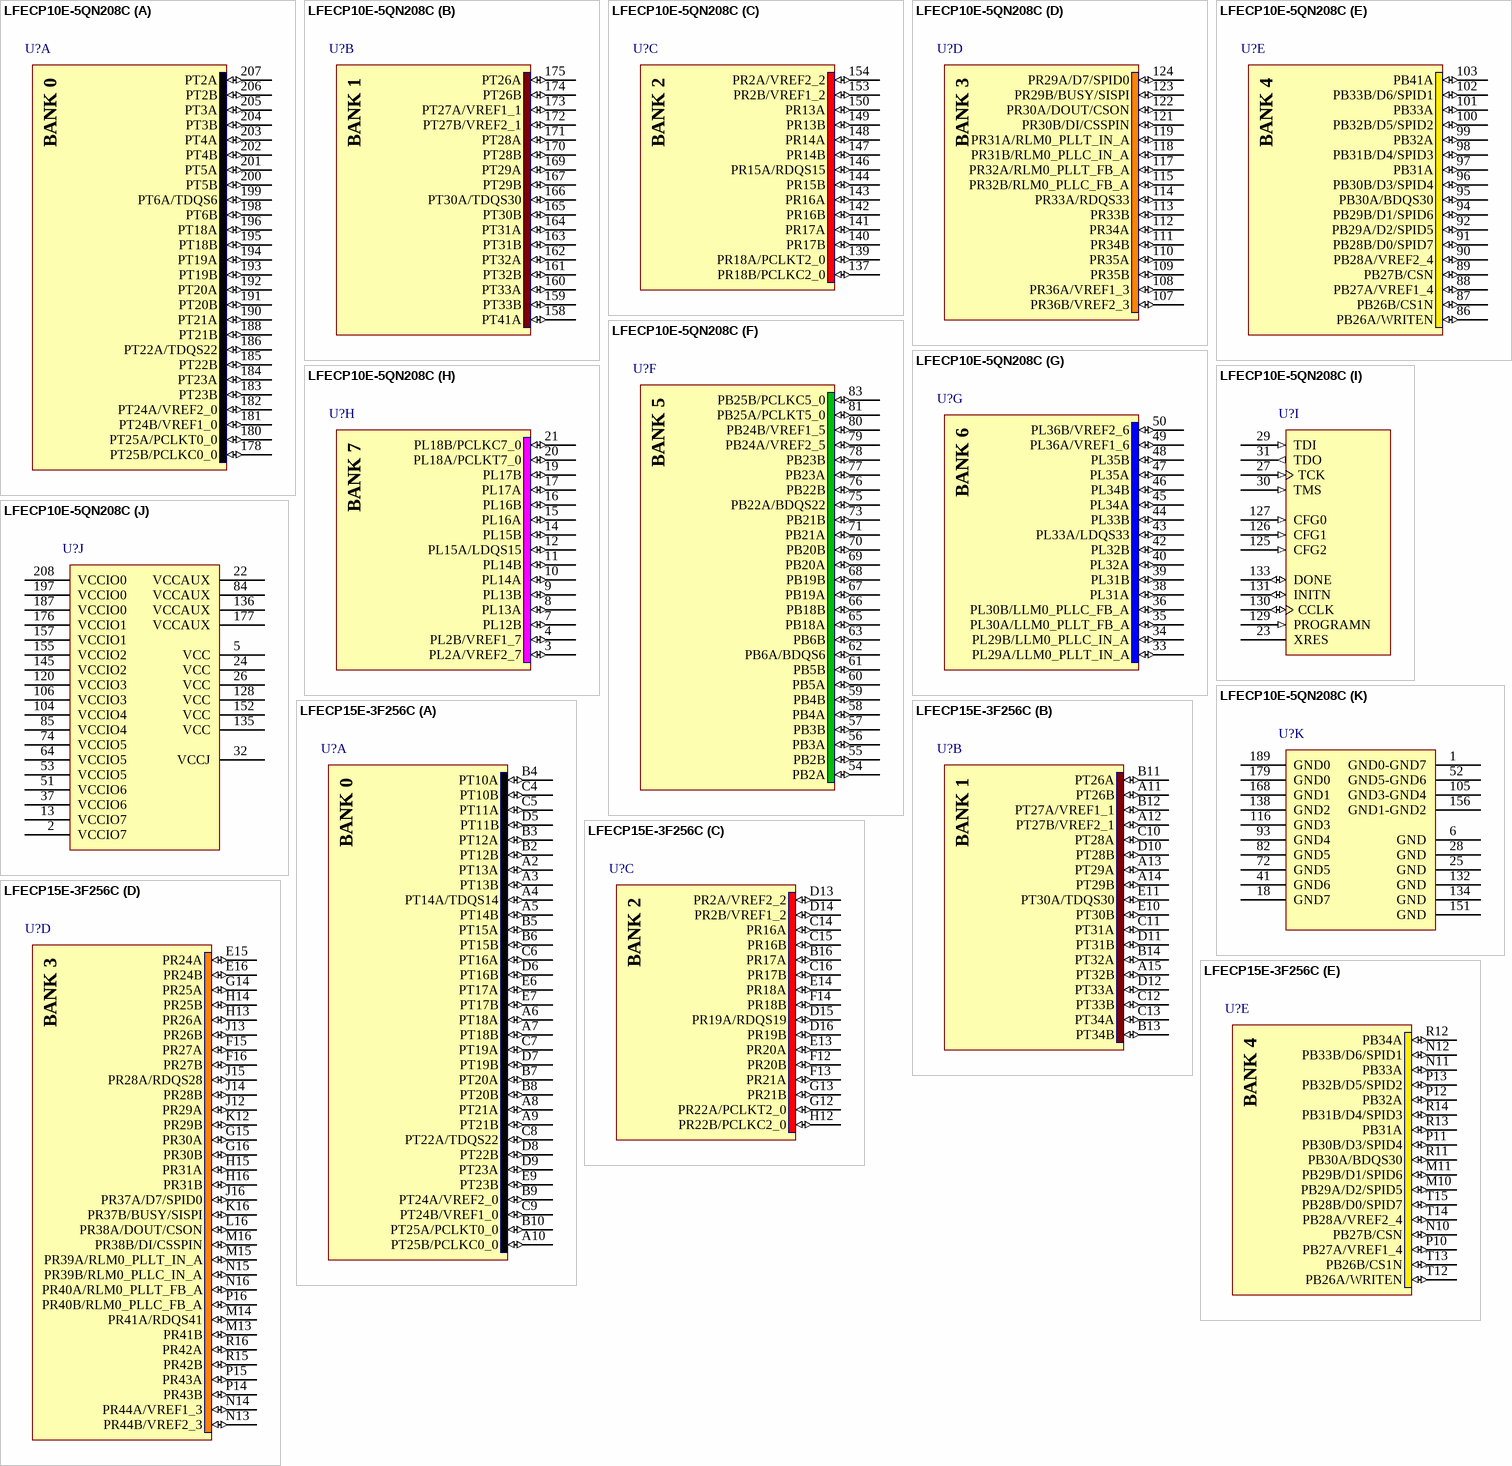
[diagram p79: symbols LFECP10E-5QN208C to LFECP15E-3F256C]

## LFECP10E-5QN208C
designator U?
ECP 1.2V FPGA, 147 I/Os, 4 PLLs, 10.2K LUTs, 5 sysDSP Blocks, 20 18x18 Multipliers, 208-Pin PQFP, Pb-Free, Speed Grade 5, Commercial Temperature Grade; Note: Pins 1, 52, 105 and 156 are double bonded.
footprint PQFP208_N (Shrink QFP, 208-Leads, Body 28x28mm, Pitch 0.5mm, IPC Medium Density)
footprint PQFP208_L (Shrink QFP, 208-Leads, Body 28x28mm, Pitch 0.5mm, IPC High Density)
footprint PQFP208_M (Shrink QFP, 208-Leads, Body 28x28mm, Pitch 0.5mm, IPC Low Density)
3D model ECP10E-PQFP-208 (208-Pin Plastic Quad Flat Pack (PQFP208))
part A pins: 178 PT25B/PCLKC0_0 (io), 180 PT25A/PCLKT0_0 (io), 181 PT24B/VREF1_0 (io), 182 PT24A/VREF2_0 (io), 183 PT23B (io), 184 PT23A (io), 185 PT22B (io), 186 PT22A/TDQS22 (io), 188 PT21B (io), 190 PT21A (io), 191 PT20B (io), 192 PT20A (io), 193 PT19B (io), 194 PT19A (io), 195 PT18B (io), 196 PT18A (io), 198 PT6B (io), 199 PT6A/TDQS6 (io), 200 PT5B (io), 201 PT5A (io), 202 PT4B (io), 203 PT4A (io), 204 PT3B (io), 205 PT3A (io), 206 PT2B (io), 207 PT2A (io)
part B pins: 158 PT41A (io), 159 PT33B (io), 160 PT33A (io), 161 PT32B (io), 162 PT32A (io), 163 PT31B (io), 164 PT31A (io), 165 PT30B (io), 166 PT30A/TDQS30 (io), 167 PT29B (io), 169 PT29A (io), 170 PT28B (io), 171 PT28A (io), 172 PT27B/VREF2_1 (io), 173 PT27A/VREF1_1 (io), 174 PT26B (io), 175 PT26A (io)
part C pins: 137 PR18B/PCLKC2_0 (io), 139 PR18A/PCLKT2_0 (io), 140 PR17B (io), 141 PR17A (io), 142 PR16B (io), 143 PR16A (io), 144 PR15B (io), 146 PR15A/RDQS15 (io), 147 PR14B (io), 148 PR14A (io), 149 PR13B (io), 150 PR13A (io), 153 PR2B/VREF1_2 (io), 154 PR2A/VREF2_2 (io)
part D pins: 107 PR36B/VREF2_3 (io), 108 PR36A/VREF1_3 (io), 109 PR35B (io), 110 PR35A (io), 111 PR34B (io), 112 PR34A (io), 113 PR33B (io), 114 PR33A/RDQS33 (io), 115 PR32B/RLM0_PLLC_FB_A (io), 117 PR32A/RLM0_PLLT_FB_A (io), 118 PR31B/RLM0_PLLC_IN_A (io), 119 PR31A/RLM0_PLLT_IN_A (io), 121 PR30B/DI/CSSPIN (io), 122 PR30A/DOUT/CSON (io), 123 PR29B/BUSY/SISPI (io), 124 PR29A/D7/SPID0 (io)
part E pins: 86 PB26A/WRITEN (io), 87 PB26B/CS1N (io), 88 PB27A/VREF1_4 (io), 89 PB27B/CSN (io), 90 PB28A/VREF2_4 (io), 91 PB28B/D0/SPID7 (io), 92 PB29A/D2/SPID5 (io), 94 PB29B/D1/SPID6 (io), 95 PB30A/BDQS30 (io), 96 PB30B/D3/SPID4 (io), 97 PB31A (io), 98 PB31B/D4/SPID3 (io), 99 PB32A (io), 100 PB32B/D5/SPID2 (io), 101 PB33A (io), 102 PB33B/D6/SPID1 (io), 103 PB41A (io)
part F pins: 54 PB2A (io), 55 PB2B (io), 56 PB3A (io), 57 PB3B (io), 58 PB4A (io), 59 PB4B (io), 60 PB5A (io), 61 PB5B (io), 62 PB6A/BDQS6 (io), 63 PB6B (io), 65 PB18A (io), 66 PB18B (io), 67 PB19A (io), 68 PB19B (io), 69 PB20A (io), 70 PB20B (io), 71 PB21A (io), 73 PB21B (io), 75 PB22A/BDQS22 (io), 76 PB22B (io), 77 PB23A (io), 78 PB23B (io), 79 PB24A/VREF2_5 (io), 80 PB24B/VREF1_5 (io), 81 PB25A/PCLKT5_0 (io), 83 PB25B/PCLKC5_0 (io)
part G pins: 33 PL29A/LLM0_PLLT_IN_A (io), 34 PL29B/LLM0_PLLC_IN_A (io), 35 PL30A/LLM0_PLLT_FB_A (io), 36 PL30B/LLM0_PLLC_FB_A (io), 38 PL31A (io), 39 PL31B (io), 40 PL32A (io), 42 PL32B (io), 43 PL33A/LDQS33 (io), 44 PL33B (io), 45 PL34A (io), 46 PL34B (io), 47 PL35A (io), 48 PL35B (io), 49 PL36A/VREF1_6 (io), 50 PL36B/VREF2_6 (io)
part H pins: 3 PL2A/VREF2_7 (io), 4 PL2B/VREF1_7 (io), 7 PL12B (io), 8 PL13A (io), 9 PL13B (io), 10 PL14A (io), 11 PL14B (io), 12 PL15A/LDQS15 (io), 14 PL15B (io), 15 PL16A (io), 16 PL16B (io), 17 PL17A (io), 19 PL17B (io), 20 PL18A/PCLKT7_0 (io), 21 PL18B/PCLKC7_0 (io)
part I pins: 23 XRES, 27 TCK (in), 29 TDI (in), 30 TMS (in), 31 TDO (out), 125 CFG2 (in), 126 CFG1 (in), 127 CFG0 (in), 129 PROGRAMN (in), 130 CCLK (io), 131 INITN (io), 133 DONE (io)
part J pins: 2 VCCIO7 (power), 5 VCC (power), 13 VCCIO7 (power), 22 VCCAUX (power), 24 VCC (power), 26 VCC (power), 32 VCCJ (power), 37 VCCIO6 (power), 51 VCCIO6 (power), 53 VCCIO5 (power), 64 VCCIO5 (power), 74 VCCIO5 (power), 84 VCCAUX (power), 85 VCCIO4 (power), 104 VCCIO4 (power), 106 VCCIO3 (power), 120 VCCIO3 (power), 128 VCC (power), 135 VCC (power), 136 VCCAUX (power), 145 VCCIO2 (power), 152 VCC (power), 155 VCCIO2 (power), 157 VCCIO1 (power), 176 VCCIO1 (power), 177 VCCAUX (power), 187 VCCIO0 (power), 197 VCCIO0 (power), 208 VCCIO0 (power)
part K pins: 1 GND0-GND7 (power), 6 GND (power), 18 GND7 (power), 25 GND (power), 28 GND (power), 41 GND6 (power), 52 GND5-GND6 (power), 72 GND5 (power), 82 GND5 (power), 93 GND4 (power), 105 GND3-GND4 (power), 116 GND3 (power), 132 GND (power), 134 GND (power), 138 GND2 (power), 151 GND (power), 156 GND1-GND2 (power), 168 GND1 (power), 179 GND0 (power), 189 GND0 (power)

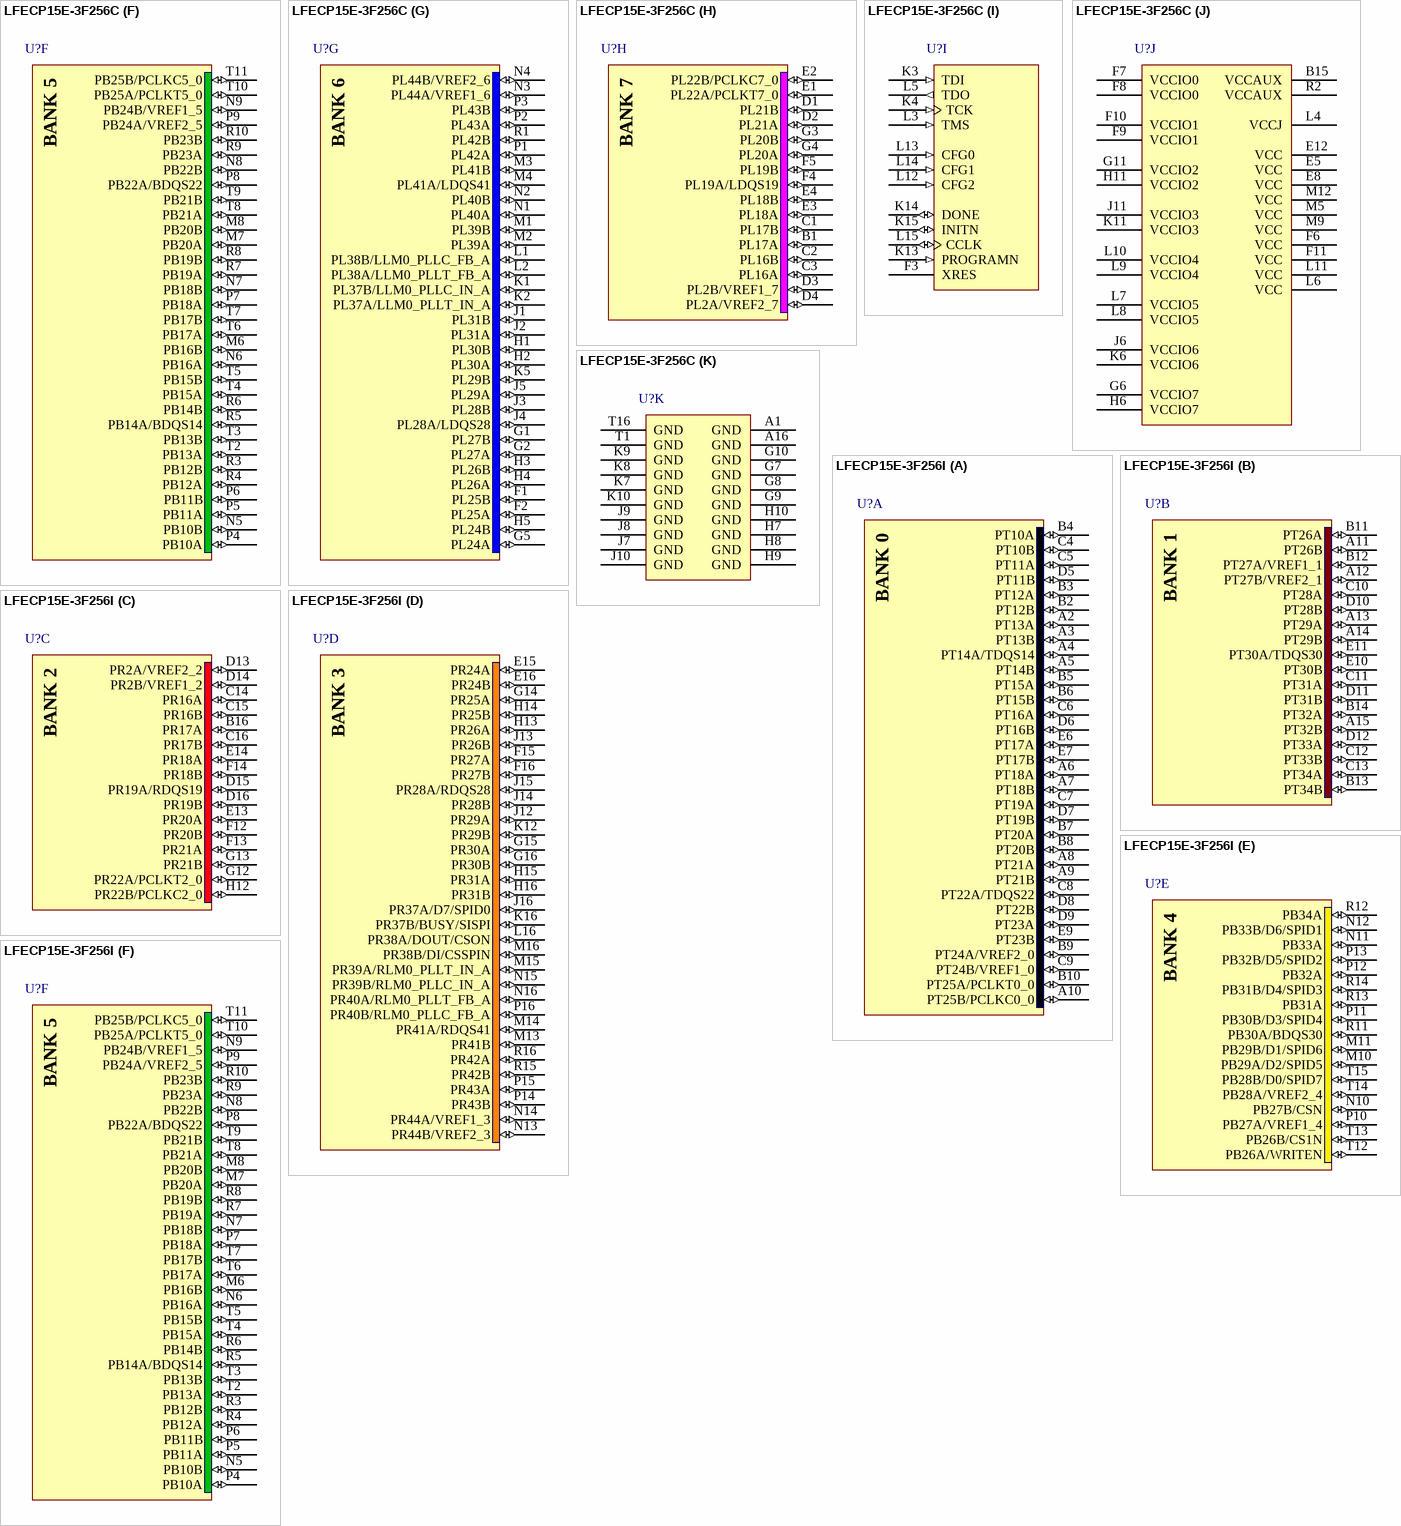
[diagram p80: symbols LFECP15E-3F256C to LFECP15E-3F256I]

## LFECP15E-3F256C
designator U?
ECP 1.2V FPGA, 192 I/Os, 4 PLLs, 15.3K LUTs, 6 sysDSP Blocks, 24 18x18 Multipliers, 256-Pin fpBGA, Speed Grade 3, Commercial Temperature Grade
footprint fpBGA256 (BGA, 256-Leads, Body 17x17mm, Pitch 1mm)
3D model ECP15E-fpBGA256 (256-Ball Fine Pitch Ball Grid Array (fpBGA256))
part A pins: A2 PT13A (io), A3 PT13B (io), A4 PT14A/TDQS14 (io), A5 PT14B (io), A6 PT18A (io), A7 PT18B (io), A8 PT21A (io), A9 PT21B (io), A10 PT25B/PCLKC0_0 (io), B2 PT12B (io), B3 PT12A (io), B4 PT10A (io), B5 PT15A (io), B6 PT15B (io), B7 PT20A (io), B8 PT20B (io), B9 PT24A/VREF2_0 (io), B10 PT25A/PCLKT0_0 (io), C4 PT10B (io), C5 PT11A (io), C6 PT16A (io), C7 PT19A (io), C8 PT22A/TDQS22 (io), C9 PT24B/VREF1_0 (io), D5 PT11B (io), D6 PT16B (io), D7 PT19B (io), D8 PT22B (io), D9 PT23A (io), E6 PT17A (io), E7 PT17B (io), E9 PT23B (io)
part B pins: A11 PT26B (io), A12 PT27B/VREF2_1 (io), A13 PT29A (io), A14 PT29B (io), A15 PT32B (io), B11 PT26A (io), B12 PT27A/VREF1_1 (io), B13 PT34B (io), B14 PT32A (io), C10 PT28A (io), C11 PT31A (io), C12 PT33B (io), C13 PT34A (io), D10 PT28B (io), D11 PT31B (io), D12 PT33A (io), E10 PT30B (io), E11 PT30A/TDQS30 (io)
part C pins: B16 PR17A (io), C14 PR16A (io), C15 PR16B (io), C16 PR17B (io), D13 PR2A/VREF2_2 (io), D14 PR2B/VREF1_2 (io), D15 PR19A/RDQS19 (io), D16 PR19B (io), E13 PR20A (io), E14 PR18A (io), F12 PR20B (io), F13 PR21A (io), F14 PR18B (io), G12 PR22A/PCLKT2_0 (io), G13 PR21B (io), H12 PR22B/PCLKC2_0 (io)
part D pins: E15 PR24A (io), E16 PR24B (io), F15 PR27A (io), F16 PR27B (io), G14 PR25A (io), G15 PR30A (io), G16 PR30B (io), H13 PR26A (io), H14 PR25B (io), H15 PR31A (io), H16 PR31B (io), J12 PR29A (io), J13 PR26B (io), J14 PR28B (io), J15 PR28A/RDQS28 (io), J16 PR37A/D7/SPID0 (io), K12 PR29B (io), K16 PR37B/BUSY/SISPI (io), L16 PR38A/DOUT/CSON (io), M13 PR41B (io), M14 PR41A/RDQS41 (io), M15 PR39A/RLM0_PLLT_IN_A (io), M16 PR38B/DI/CSSPIN (io), N13 PR44B/VREF2_3 (io), N14 PR44A/VREF1_3 (io), N15 PR39B/RLM0_PLLC_IN_A (io), N16 PR40A/RLM0_PLLT_FB_A (io), P14 PR43B (io), P15 PR43A (io), P16 PR40B/RLM0_PLLC_FB_A (io), R15 PR42B (io), R16 PR42A (io)
part E pins: M10 PB29A/D2/SPID5 (io), M11 PB29B/D1/SPID6 (io), N10 PB27B/CSN (io), N11 PB33A (io), N12 PB33B/D6/SPID1 (io), P10 PB27A/VREF1_4 (io), P11 PB30B/D3/SPID4 (io), P12 PB32A (io), P13 PB32B/D5/SPID2 (io), R11 PB30A/BDQS30 (io), R12 PB34A (io), R13 PB31A (io), R14 PB31B/D4/SPID3 (io), T12 PB26A/WRITEN (io), T13 PB26B/CS1N (io), T14 PB28A/VREF2_4 (io), T15 PB28B/D0/SPID7 (io)
part F pins: M6 PB16B (io), M7 PB20A (io), M8 PB20B (io), N5 PB10B (io), N6 PB16A (io), N7 PB18B (io), N8 PB22B (io), N9 PB24B/VREF1_5 (io), P4 PB10A (io), P5 PB11A (io), P6 PB11B (io), P7 PB18A (io), P8 PB22A/BDQS22 (io), P9 PB24A/VREF2_5 (io), R3 PB12B (io), R4 PB12A (io), R5 PB14A/BDQS14 (io), R6 PB14B (io), R7 PB19A (io), R8 PB19B (io), R9 PB23A (io), R10 PB23B (io), T2 PB13A (io), T3 PB13B (io), T4 PB15A (io), T5 PB15B (io), T6 PB17A (io), T7 PB17B (io), T8 PB21A (io), T9 PB21B (io), T10 PB25A/PCLKT5_0 (io), T11 PB25B/PCLKC5_0 (io)
part G pins: F1 PL25B (io), F2 PL25A (io), G1 PL27B (io), G2 PL27A (io), G5 PL24A (io), H1 PL30B (io), H2 PL30A (io), H3 PL26B (io), H4 PL26A (io), H5 PL24B (io), J1 PL31B (io), J2 PL31A (io), J3 PL28B (io), J4 PL28A/LDQS28 (io), J5 PL29A (io), K1 PL37B/LLM0_PLLC_IN_A (io), K2 PL37A/LLM0_PLLT_IN_A (io), K5 PL29B (io), L1 PL38B/LLM0_PLLC_FB_A (io), L2 PL38A/LLM0_PLLT_FB_A (io), M1 PL39B (io), M2 PL39A (io), M3 PL41B (io), M4 PL41A/LDQS41 (io), N1 PL40A (io), N2 PL40B (io), N3 PL44A/VREF1_6 (io), N4 PL44B/VREF2_6 (io), P1 PL42A (io), P2 PL43A (io), P3 PL43B (io), R1 PL42B (io)
part H pins: B1 PL17A (io), C1 PL17B (io), C2 PL16B (io), C3 PL16A (io), D1 PL21B (io), D2 PL21A (io), D3 PL2B/VREF1_7 (io), D4 PL2A/VREF2_7 (io), E1 PL22A/PCLKT7_0 (io), E2 PL22B/PCLKC7_0 (io), E3 PL18A (io), E4 PL18B (io), F4 PL19A/LDQS19 (io), F5 PL19B (io), G3 PL20B (io), G4 PL20A (io)
part I pins: F3 XRES, K3 TDI (in), K4 TCK (in), K13 PROGRAMN (in), K14 DONE (io), K15 INITN (io), L3 TMS (in), L5 TDO (out), L12 CFG2 (in), L13 CFG0 (in), L14 CFG1 (in), L15 CCLK (io)
part J pins: B15 VCCAUX (power), E5 VCC (power), E8 VCC (power), E12 VCC (power), F6 VCC (power), F7 VCCIO0 (power), F8 VCCIO0 (power), F9 VCCIO1 (power), F10 VCCIO1 (power), F11 VCC (power), G6 VCCIO7 (power), G11 VCCIO2 (power), H6 VCCIO7 (power), H11 VCCIO2 (power), J6 VCCIO6 (power), J11 VCCIO3 (power), K6 VCCIO6 (power), K11 VCCIO3 (power), L4 VCCJ (power), L6 VCC (power), L7 VCCIO5 (power), L8 VCCIO5 (power), L9 VCCIO4 (power), L10 VCCIO4 (power), L11 VCC (power), M5 VCC (power), M9 VCC (power), M12 VCC (power), R2 VCCAUX (power)
part K pins: A1 GND (power), A16 GND (power), G7 GND (power), G8 GND (power), G9 GND (power), G10 GND (power), H7 GND (power), H8 GND (power), H9 GND (power), H10 GND (power), J7 GND (power), J8 GND (power), J9 GND (power), J10 GND (power), K7 GND (power), K8 GND (power), K9 GND (power), K10 GND (power), T1 GND (power), T16 GND (power)

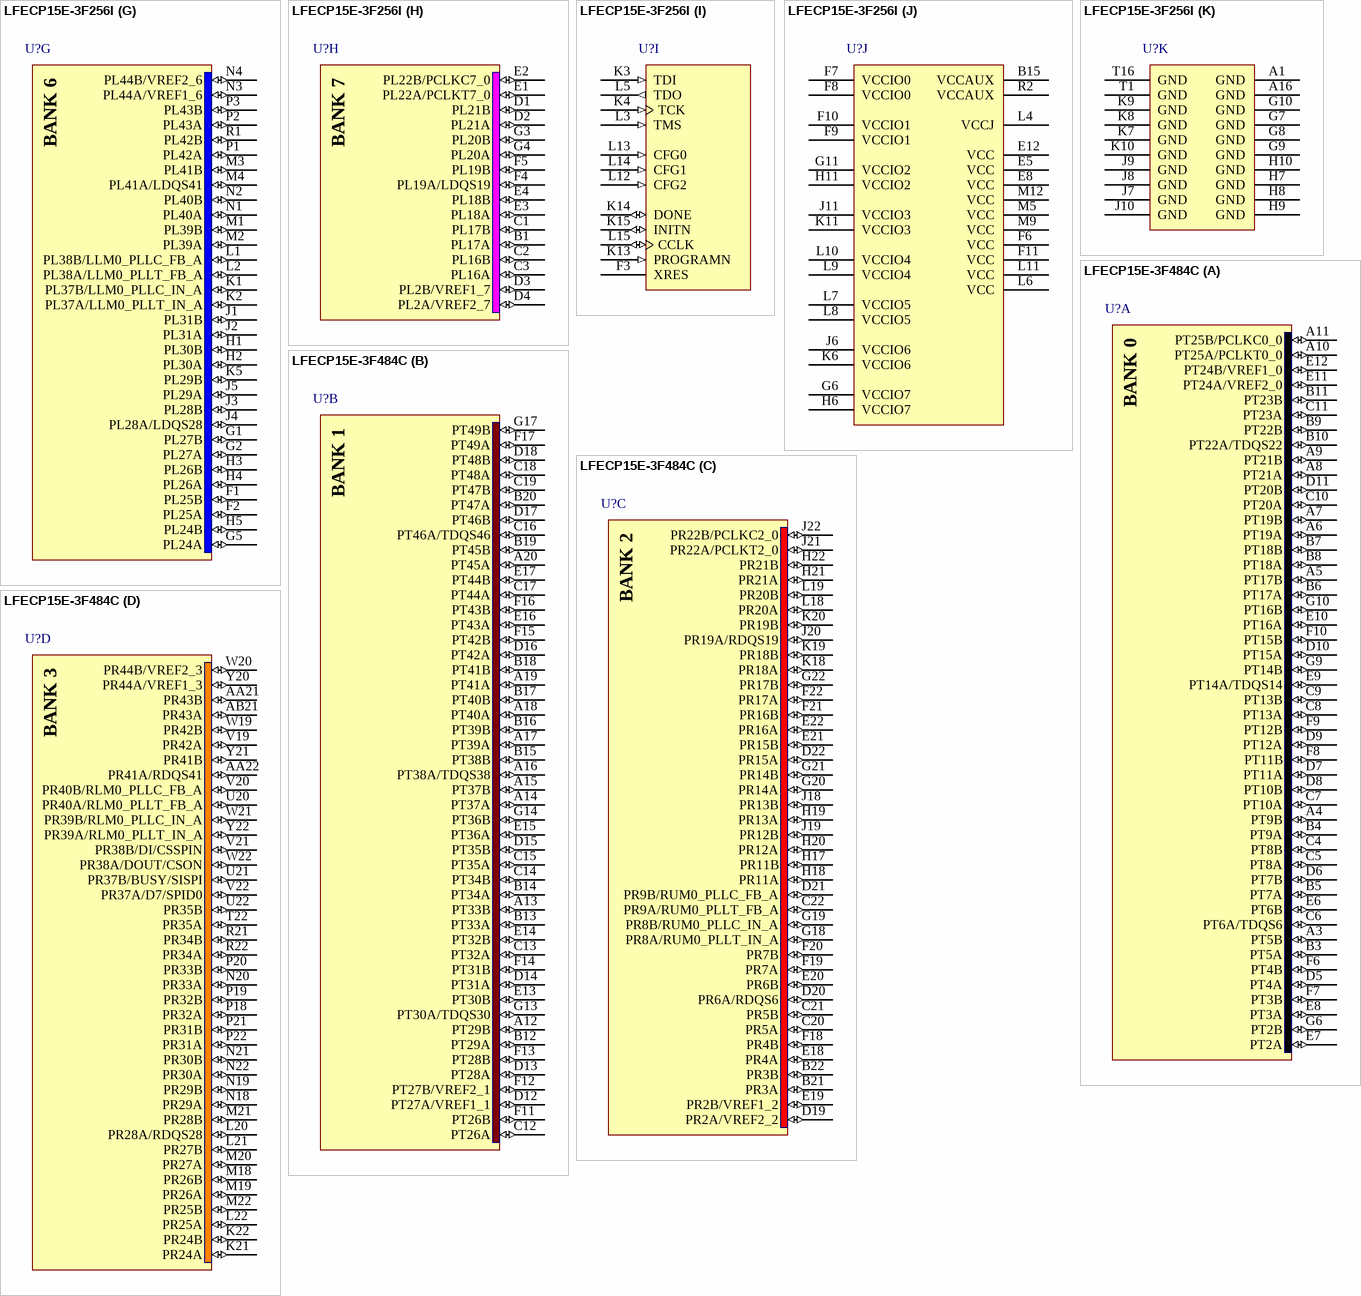
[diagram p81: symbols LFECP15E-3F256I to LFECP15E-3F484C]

## LFECP15E-3F256I
designator U?
ECP 1.2V FPGA, 192 I/Os, 4 PLLs, 15.3K LUTs, 6 sysDSP Blocks, 24 18x18 Multipliers, 256-Pin fpBGA, Speed Grade 3, Industrial Temperature Grade
footprint fpBGA256 (BGA, 256-Leads, Body 17x17mm, Pitch 1mm)
3D model ECP15E-fpBGA256 (256-Ball Fine Pitch Ball Grid Array (fpBGA256))
part A pins: A2 PT13A (io), A3 PT13B (io), A4 PT14A/TDQS14 (io), A5 PT14B (io), A6 PT18A (io), A7 PT18B (io), A8 PT21A (io), A9 PT21B (io), A10 PT25B/PCLKC0_0 (io), B2 PT12B (io), B3 PT12A (io), B4 PT10A (io), B5 PT15A (io), B6 PT15B (io), B7 PT20A (io), B8 PT20B (io), B9 PT24A/VREF2_0 (io), B10 PT25A/PCLKT0_0 (io), C4 PT10B (io), C5 PT11A (io), C6 PT16A (io), C7 PT19A (io), C8 PT22A/TDQS22 (io), C9 PT24B/VREF1_0 (io), D5 PT11B (io), D6 PT16B (io), D7 PT19B (io), D8 PT22B (io), D9 PT23A (io), E6 PT17A (io), E7 PT17B (io), E9 PT23B (io)
part B pins: A11 PT26B (io), A12 PT27B/VREF2_1 (io), A13 PT29A (io), A14 PT29B (io), A15 PT32B (io), B11 PT26A (io), B12 PT27A/VREF1_1 (io), B13 PT34B (io), B14 PT32A (io), C10 PT28A (io), C11 PT31A (io), C12 PT33B (io), C13 PT34A (io), D10 PT28B (io), D11 PT31B (io), D12 PT33A (io), E10 PT30B (io), E11 PT30A/TDQS30 (io)
part C pins: B16 PR17A (io), C14 PR16A (io), C15 PR16B (io), C16 PR17B (io), D13 PR2A/VREF2_2 (io), D14 PR2B/VREF1_2 (io), D15 PR19A/RDQS19 (io), D16 PR19B (io), E13 PR20A (io), E14 PR18A (io), F12 PR20B (io), F13 PR21A (io), F14 PR18B (io), G12 PR22A/PCLKT2_0 (io), G13 PR21B (io), H12 PR22B/PCLKC2_0 (io)
part D pins: E15 PR24A (io), E16 PR24B (io), F15 PR27A (io), F16 PR27B (io), G14 PR25A (io), G15 PR30A (io), G16 PR30B (io), H13 PR26A (io), H14 PR25B (io), H15 PR31A (io), H16 PR31B (io), J12 PR29A (io), J13 PR26B (io), J14 PR28B (io), J15 PR28A/RDQS28 (io), J16 PR37A/D7/SPID0 (io), K12 PR29B (io), K16 PR37B/BUSY/SISPI (io), L16 PR38A/DOUT/CSON (io), M13 PR41B (io), M14 PR41A/RDQS41 (io), M15 PR39A/RLM0_PLLT_IN_A (io), M16 PR38B/DI/CSSPIN (io), N13 PR44B/VREF2_3 (io), N14 PR44A/VREF1_3 (io), N15 PR39B/RLM0_PLLC_IN_A (io), N16 PR40A/RLM0_PLLT_FB_A (io), P14 PR43B (io), P15 PR43A (io), P16 PR40B/RLM0_PLLC_FB_A (io), R15 PR42B (io), R16 PR42A (io)
part E pins: M10 PB29A/D2/SPID5 (io), M11 PB29B/D1/SPID6 (io), N10 PB27B/CSN (io), N11 PB33A (io), N12 PB33B/D6/SPID1 (io), P10 PB27A/VREF1_4 (io), P11 PB30B/D3/SPID4 (io), P12 PB32A (io), P13 PB32B/D5/SPID2 (io), R11 PB30A/BDQS30 (io), R12 PB34A (io), R13 PB31A (io), R14 PB31B/D4/SPID3 (io), T12 PB26A/WRITEN (io), T13 PB26B/CS1N (io), T14 PB28A/VREF2_4 (io), T15 PB28B/D0/SPID7 (io)
part F pins: M6 PB16B (io), M7 PB20A (io), M8 PB20B (io), N5 PB10B (io), N6 PB16A (io), N7 PB18B (io), N8 PB22B (io), N9 PB24B/VREF1_5 (io), P4 PB10A (io), P5 PB11A (io), P6 PB11B (io), P7 PB18A (io), P8 PB22A/BDQS22 (io), P9 PB24A/VREF2_5 (io), R3 PB12B (io), R4 PB12A (io), R5 PB14A/BDQS14 (io), R6 PB14B (io), R7 PB19A (io), R8 PB19B (io), R9 PB23A (io), R10 PB23B (io), T2 PB13A (io), T3 PB13B (io), T4 PB15A (io), T5 PB15B (io), T6 PB17A (io), T7 PB17B (io), T8 PB21A (io), T9 PB21B (io), T10 PB25A/PCLKT5_0 (io), T11 PB25B/PCLKC5_0 (io)
part G pins: F1 PL25B (io), F2 PL25A (io), G1 PL27B (io), G2 PL27A (io), G5 PL24A (io), H1 PL30B (io), H2 PL30A (io), H3 PL26B (io), H4 PL26A (io), H5 PL24B (io), J1 PL31B (io), J2 PL31A (io), J3 PL28B (io), J4 PL28A/LDQS28 (io), J5 PL29A (io), K1 PL37B/LLM0_PLLC_IN_A (io), K2 PL37A/LLM0_PLLT_IN_A (io), K5 PL29B (io), L1 PL38B/LLM0_PLLC_FB_A (io), L2 PL38A/LLM0_PLLT_FB_A (io), M1 PL39B (io), M2 PL39A (io), M3 PL41B (io), M4 PL41A/LDQS41 (io), N1 PL40A (io), N2 PL40B (io), N3 PL44A/VREF1_6 (io), N4 PL44B/VREF2_6 (io), P1 PL42A (io), P2 PL43A (io), P3 PL43B (io), R1 PL42B (io)
part H pins: B1 PL17A (io), C1 PL17B (io), C2 PL16B (io), C3 PL16A (io), D1 PL21B (io), D2 PL21A (io), D3 PL2B/VREF1_7 (io), D4 PL2A/VREF2_7 (io), E1 PL22A/PCLKT7_0 (io), E2 PL22B/PCLKC7_0 (io), E3 PL18A (io), E4 PL18B (io), F4 PL19A/LDQS19 (io), F5 PL19B (io), G3 PL20B (io), G4 PL20A (io)
part I pins: F3 XRES, K3 TDI (in), K4 TCK (in), K13 PROGRAMN (in), K14 DONE (io), K15 INITN (io), L3 TMS (in), L5 TDO (out), L12 CFG2 (in), L13 CFG0 (in), L14 CFG1 (in), L15 CCLK (io)
part J pins: B15 VCCAUX (power), E5 VCC (power), E8 VCC (power), E12 VCC (power), F6 VCC (power), F7 VCCIO0 (power), F8 VCCIO0 (power), F9 VCCIO1 (power), F10 VCCIO1 (power), F11 VCC (power), G6 VCCIO7 (power), G11 VCCIO2 (power), H6 VCCIO7 (power), H11 VCCIO2 (power), J6 VCCIO6 (power), J11 VCCIO3 (power), K6 VCCIO6 (power), K11 VCCIO3 (power), L4 VCCJ (power), L6 VCC (power), L7 VCCIO5 (power), L8 VCCIO5 (power), L9 VCCIO4 (power), L10 VCCIO4 (power), L11 VCC (power), M5 VCC (power), M9 VCC (power), M12 VCC (power), R2 VCCAUX (power)
part K pins: A1 GND (power), A16 GND (power), G7 GND (power), G8 GND (power), G9 GND (power), G10 GND (power), H7 GND (power), H8 GND (power), H9 GND (power), H10 GND (power), J7 GND (power), J8 GND (power), J9 GND (power), J10 GND (power), K7 GND (power), K8 GND (power), K9 GND (power), K10 GND (power), T1 GND (power), T16 GND (power)

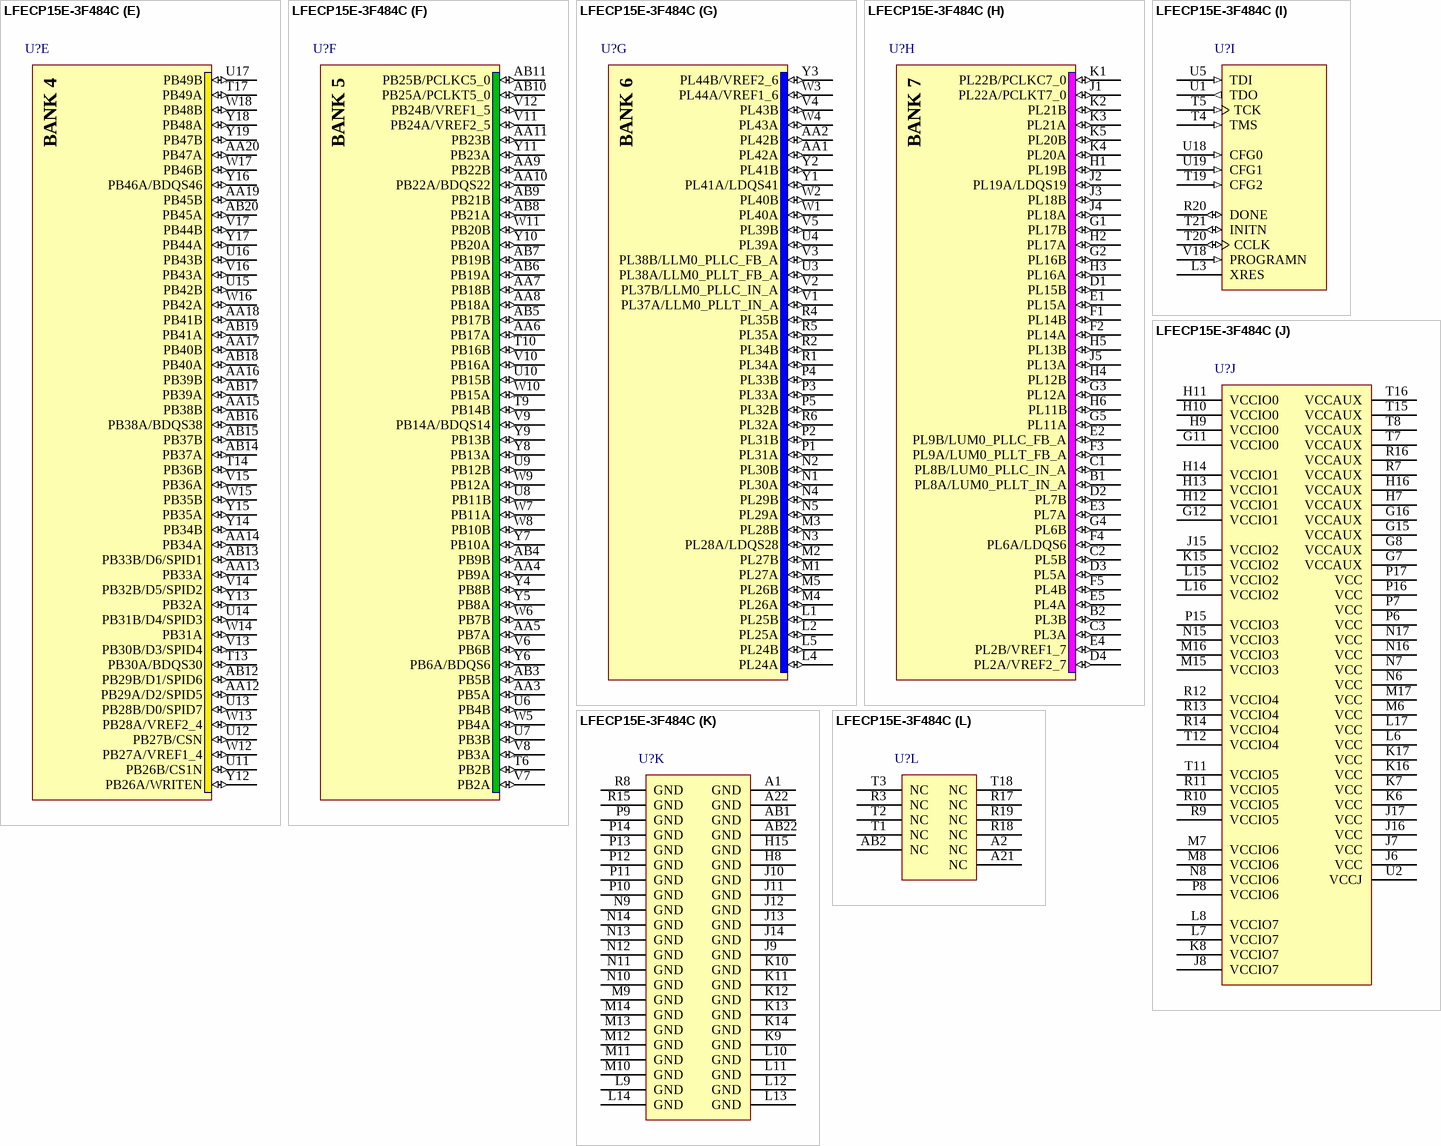
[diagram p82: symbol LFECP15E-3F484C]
